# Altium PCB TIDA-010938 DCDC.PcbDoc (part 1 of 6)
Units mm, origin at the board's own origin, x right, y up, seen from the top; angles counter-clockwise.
Board outline 280 x 174.95 mm, 4 copper layers (Top Layer, Layer 1, Layer 2, Bottom Layer), stack 1.787 mm thick; 409 components, 218 nets, 1371 pads, 2268 vias.
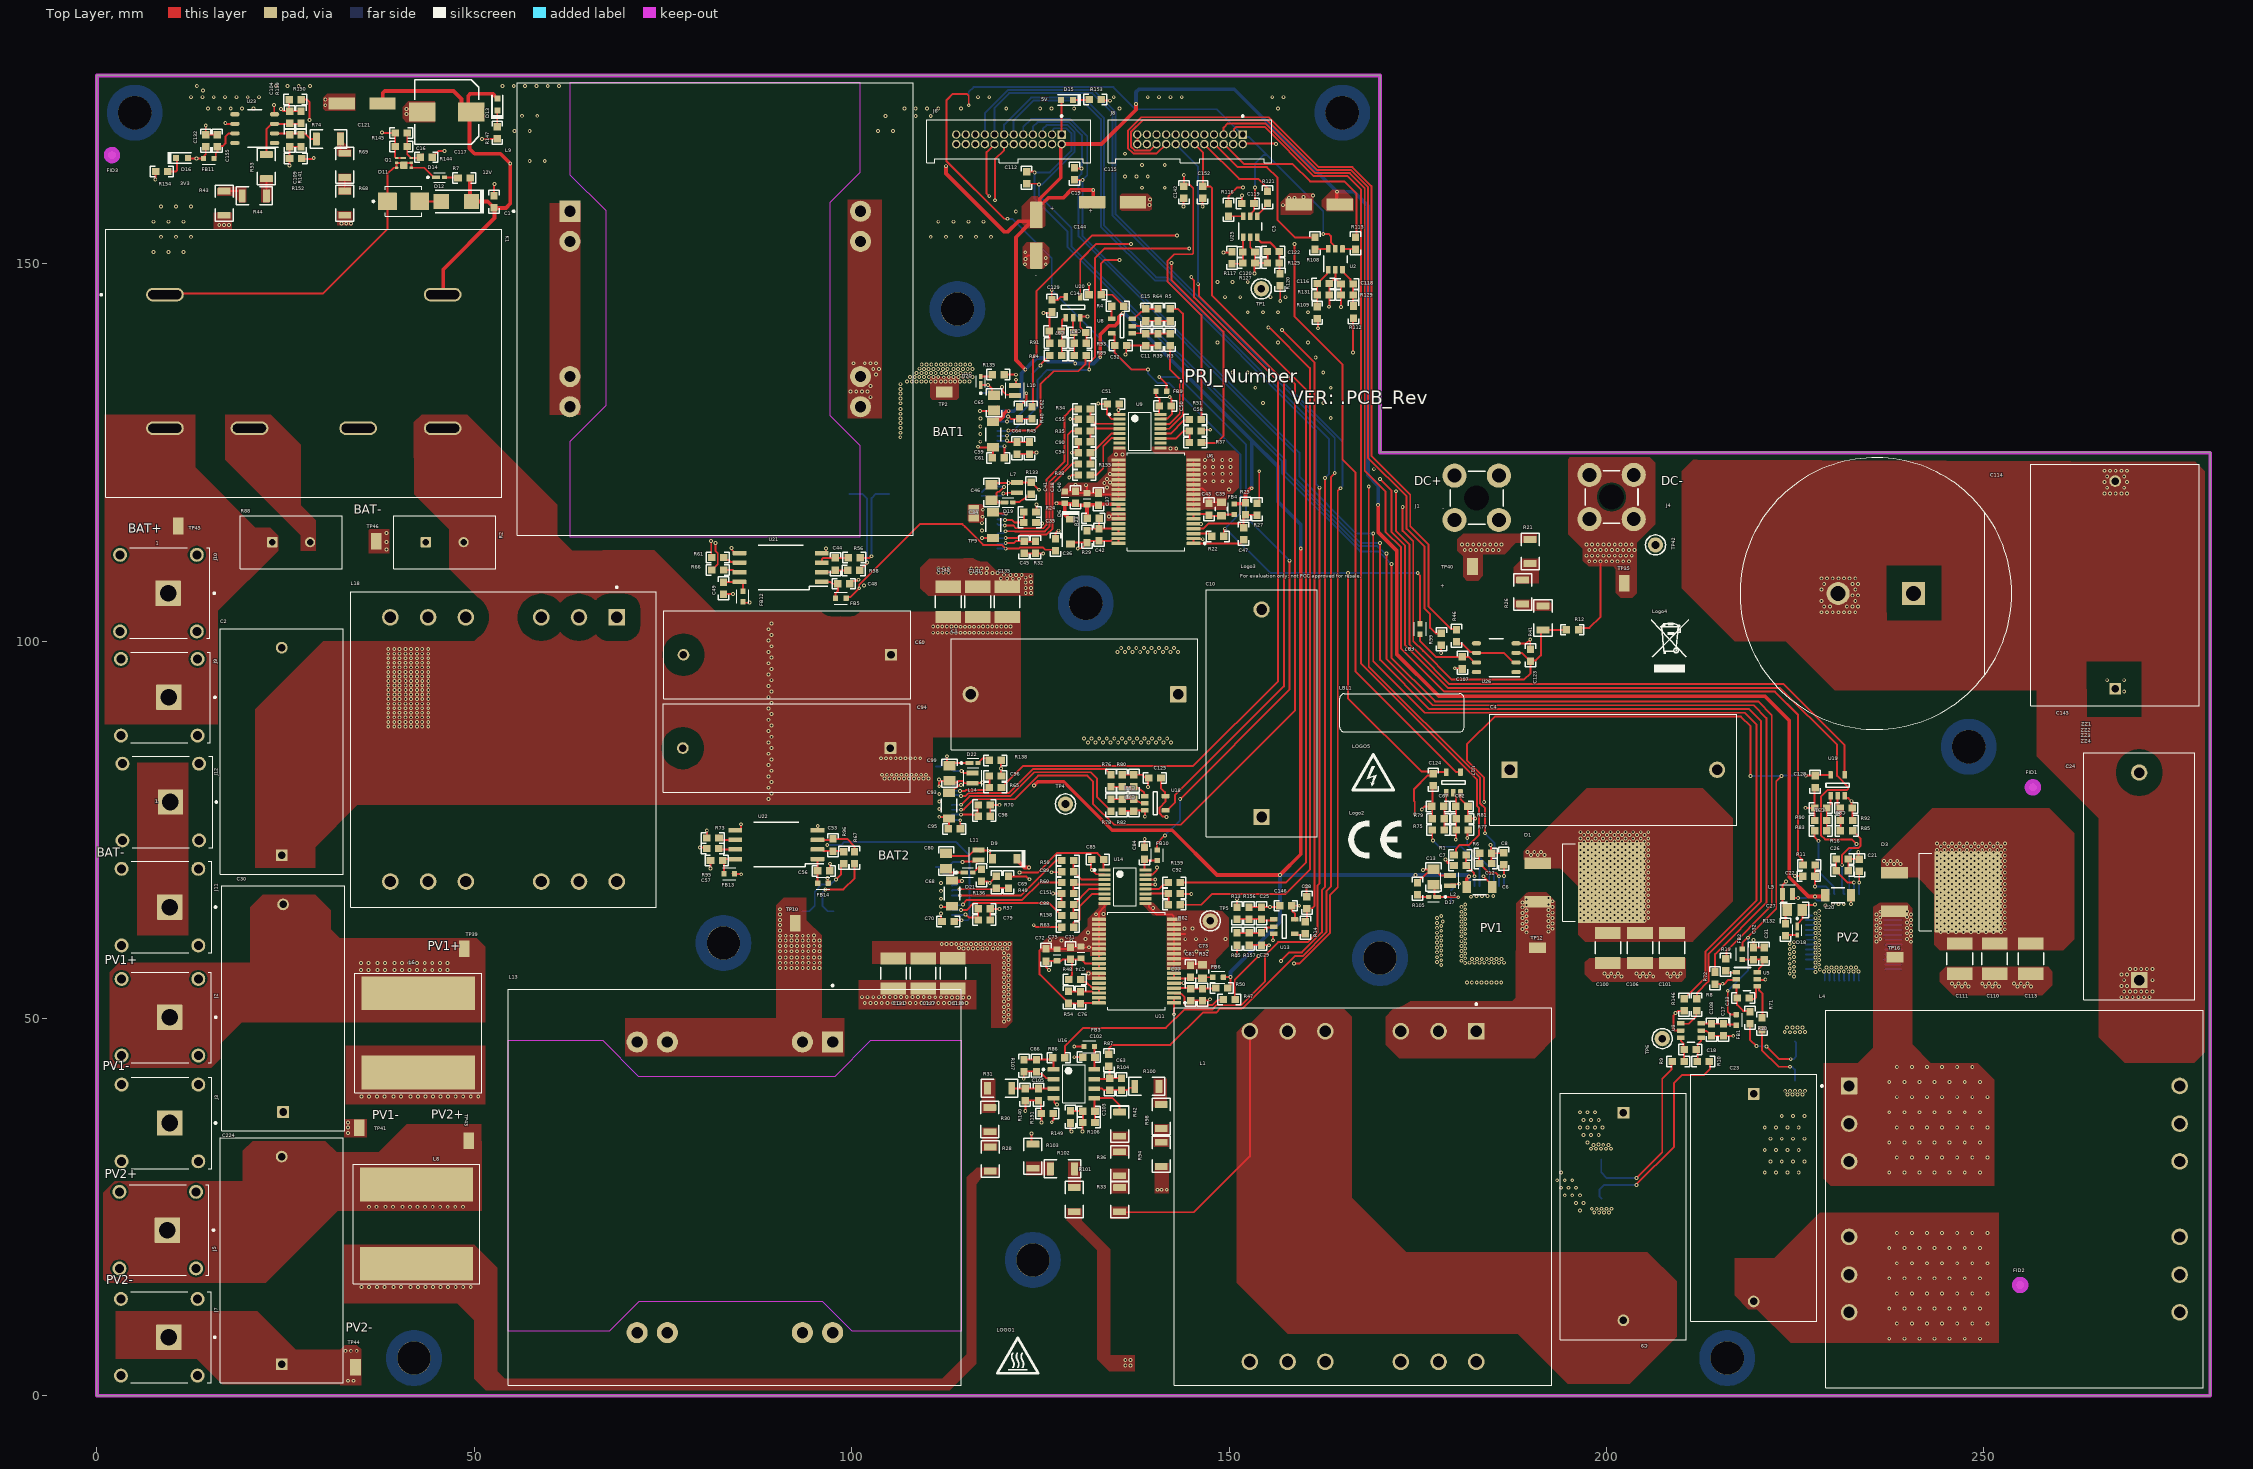
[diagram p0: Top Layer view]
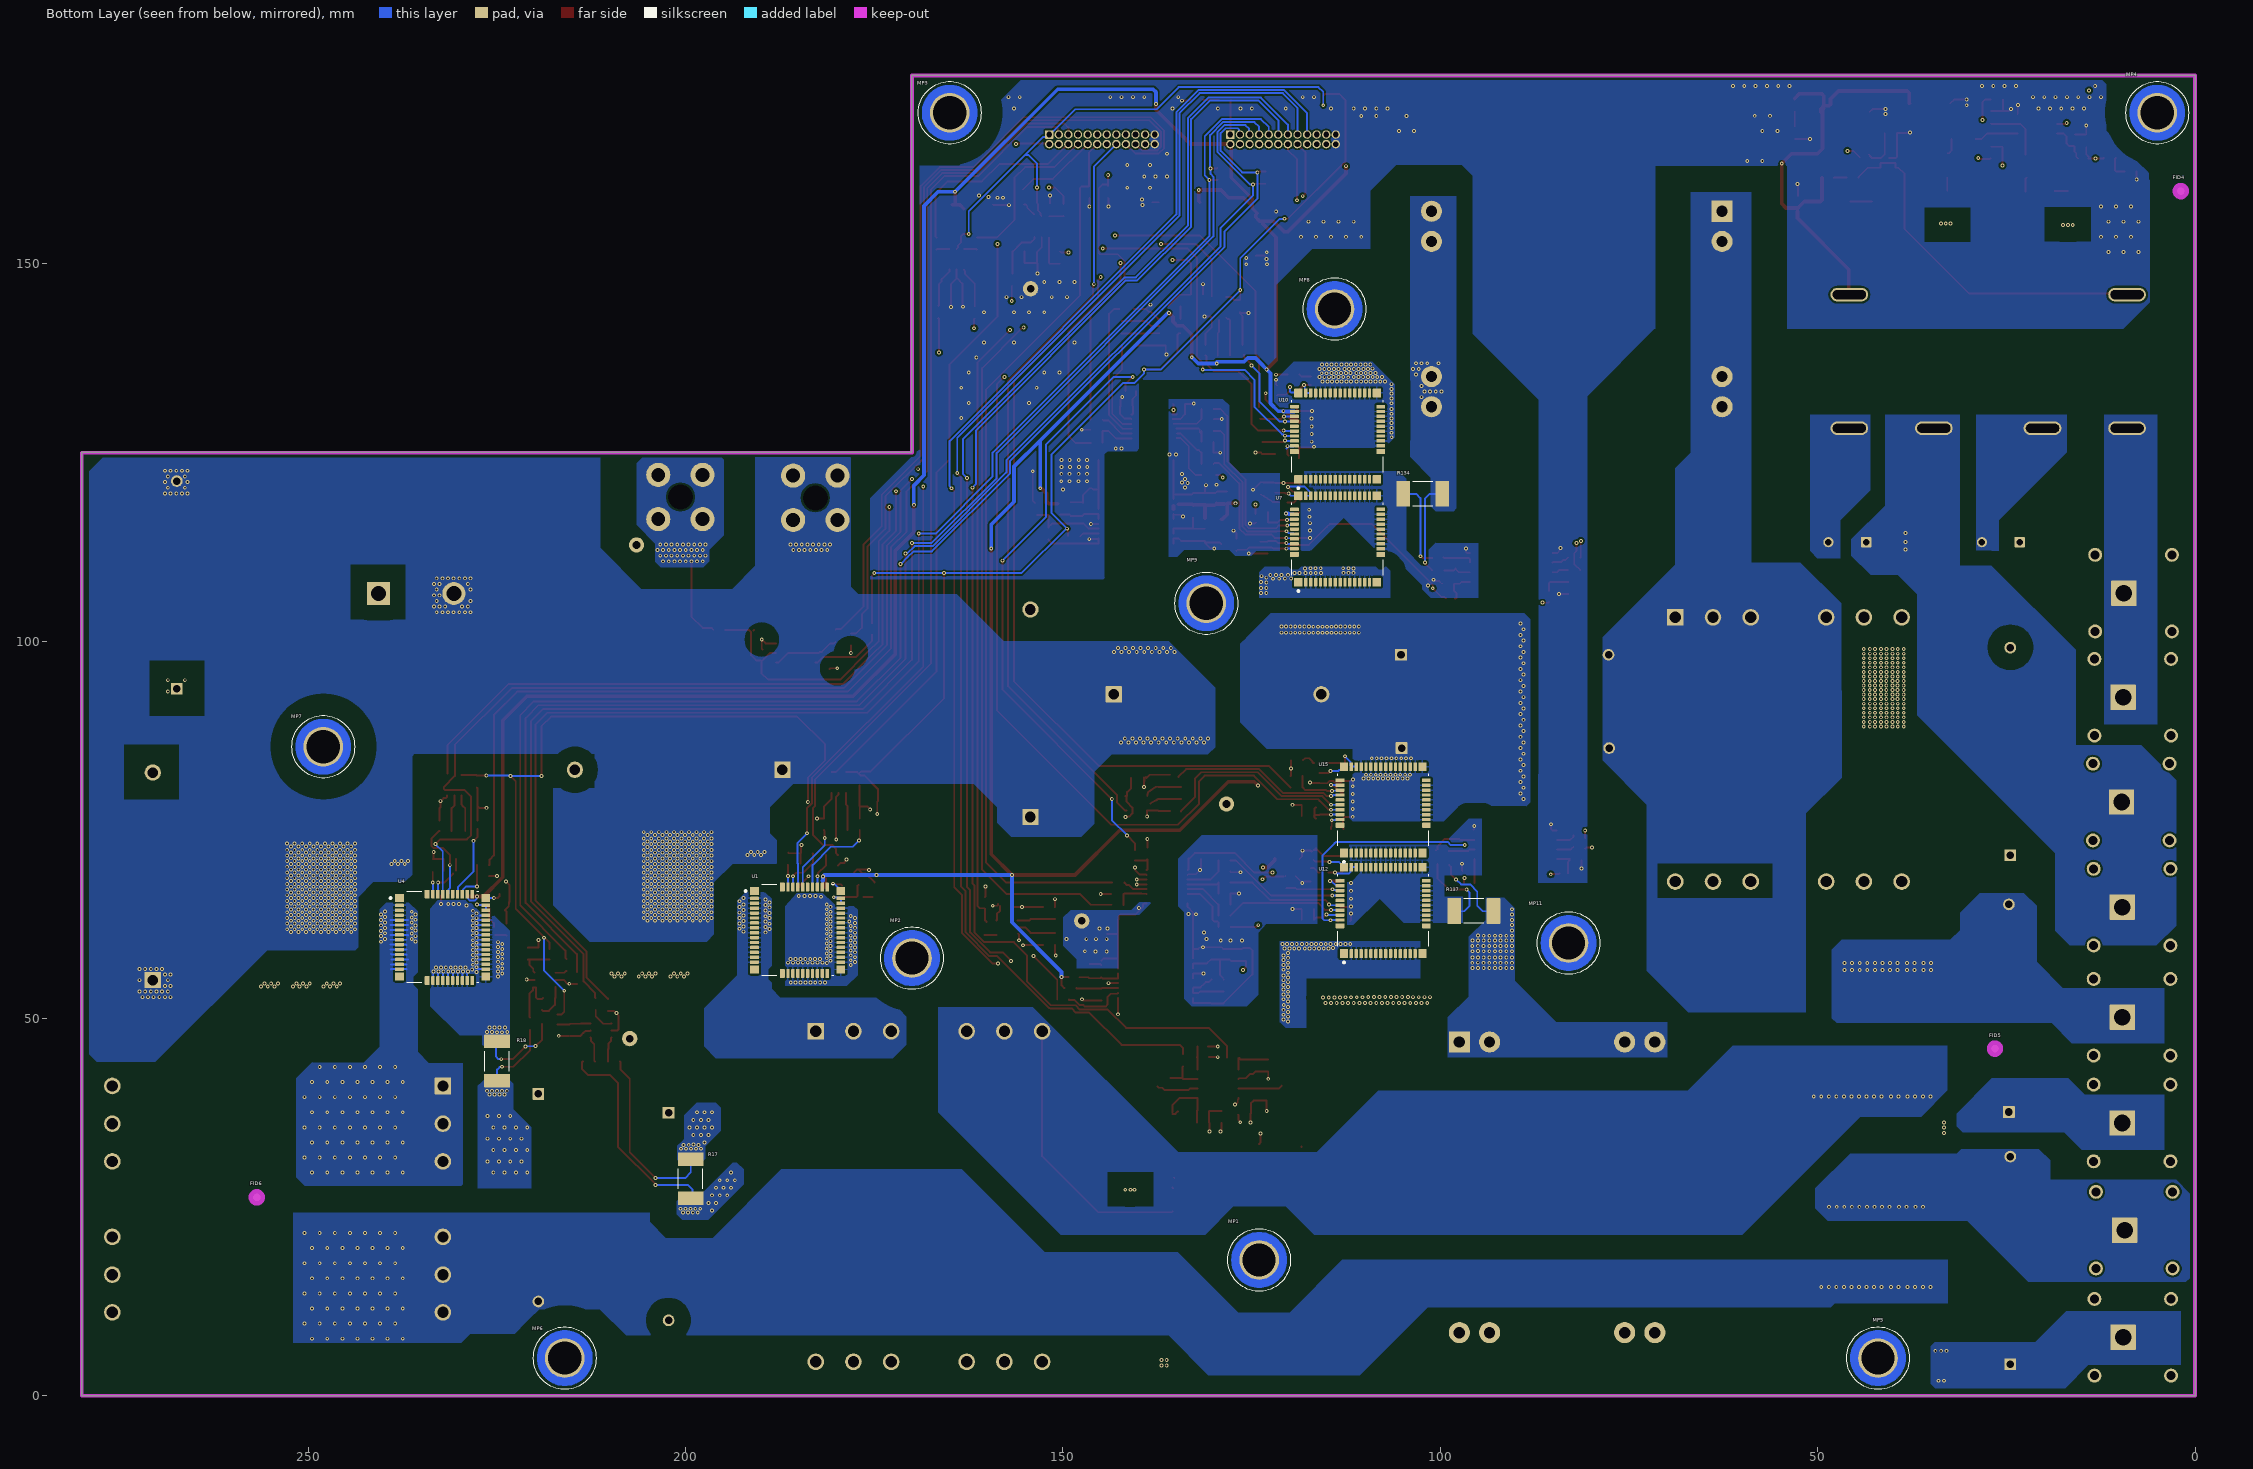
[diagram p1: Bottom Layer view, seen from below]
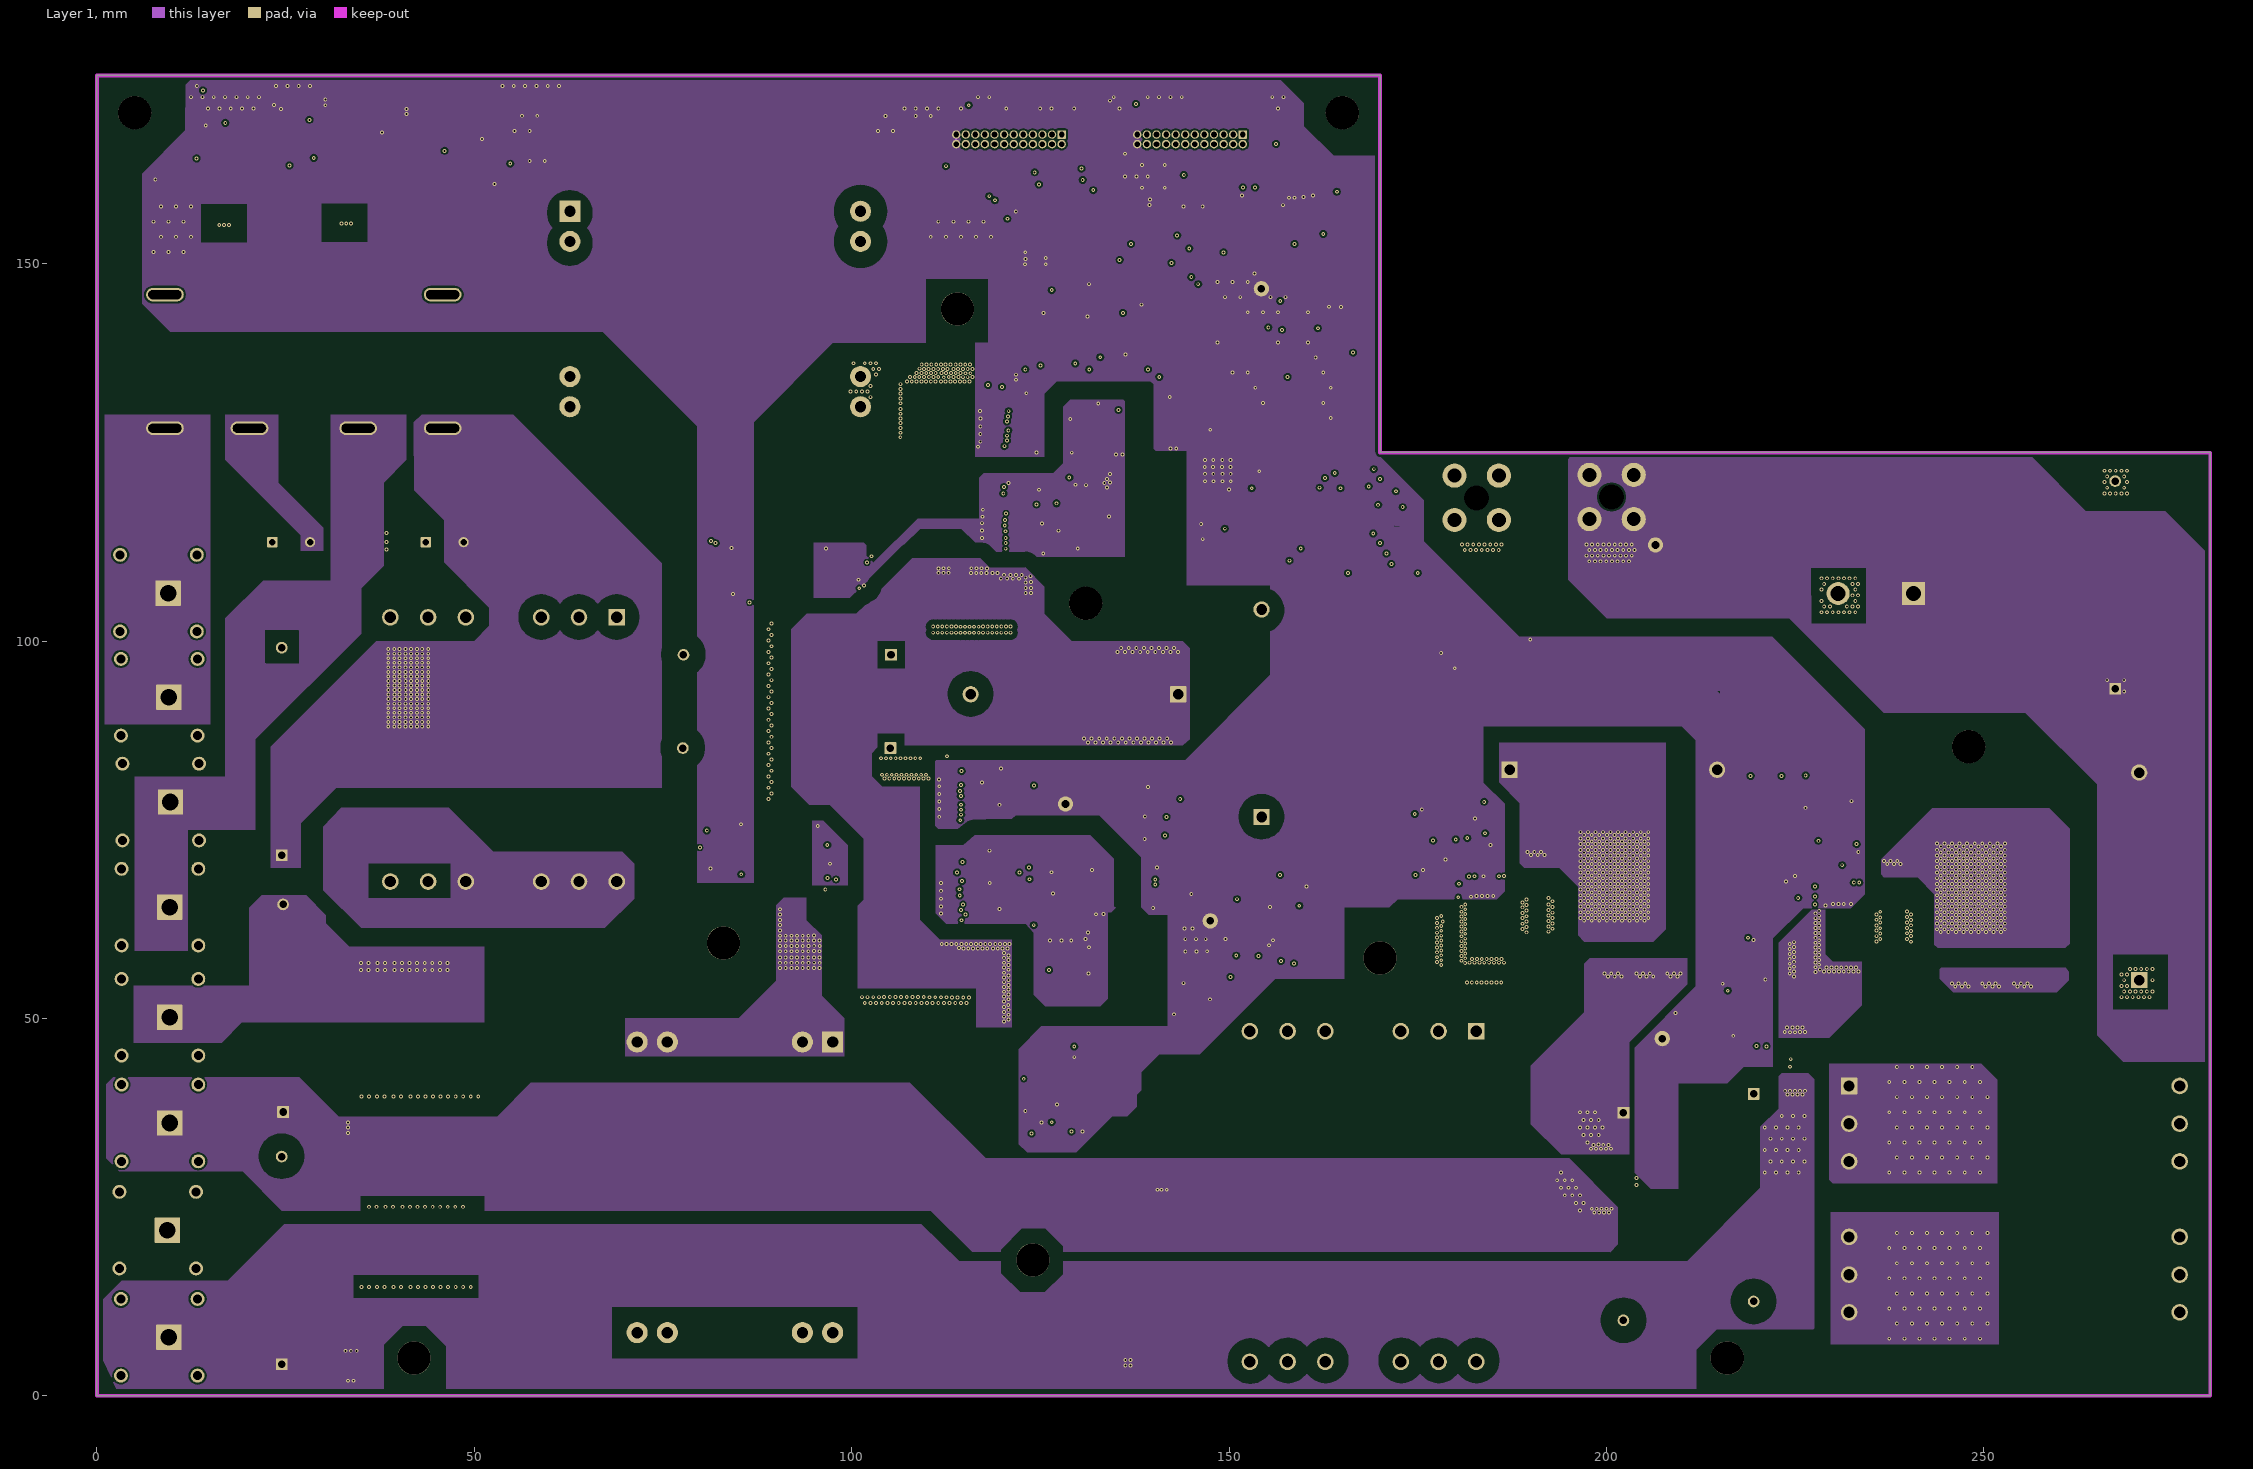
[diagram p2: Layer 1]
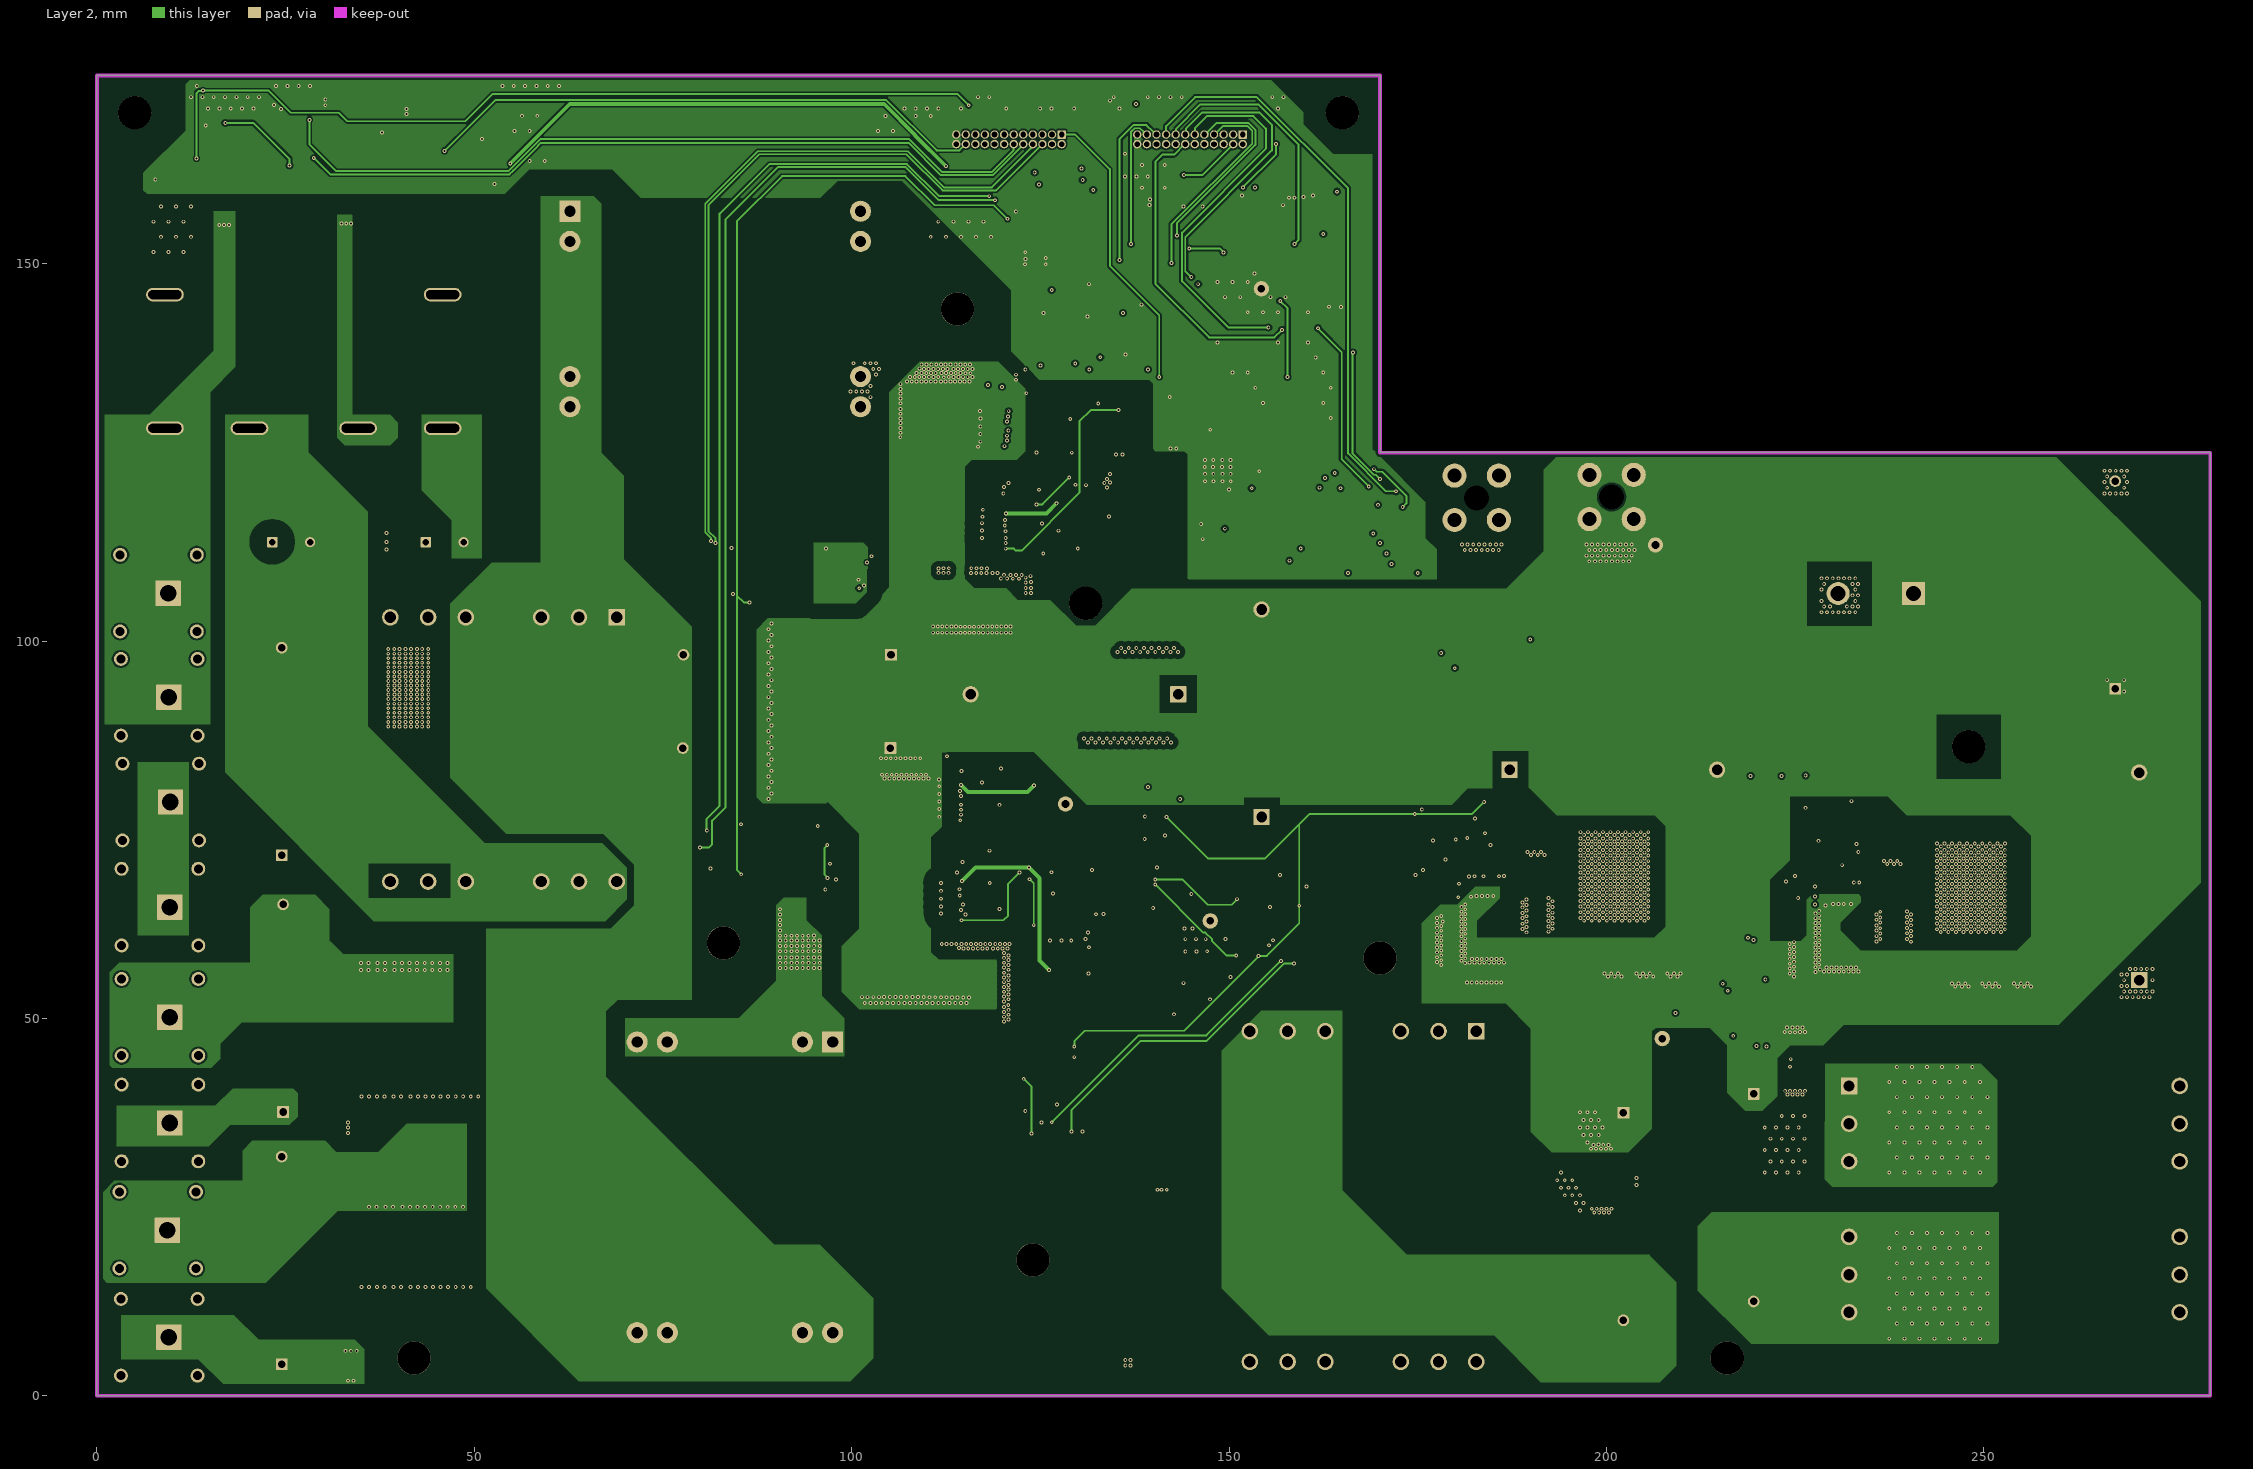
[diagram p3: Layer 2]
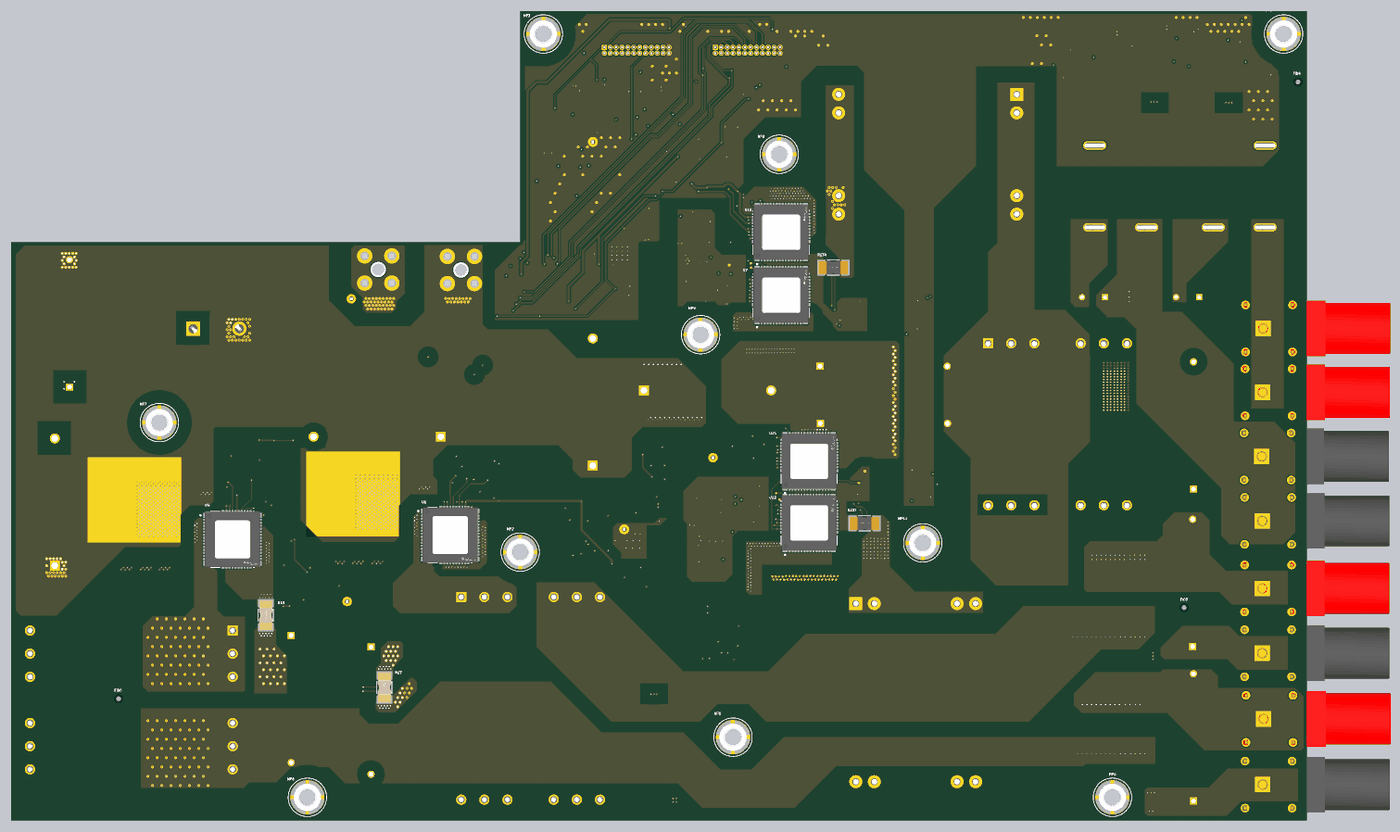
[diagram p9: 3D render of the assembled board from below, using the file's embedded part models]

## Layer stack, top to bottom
Top Solder: solder mask 0.0102, Solder Resist, Dk 3.5
Top Layer: signal copper 0.0356
Dielectric 1: prepreg 0.0711, PP-006, Dk 4.1
Layer 1: signal copper 0.035
Dielectric1: core 1.5037, FR-4 High Tg, Dk 4.8
Layer 2: signal copper 0.035
Dielectric 2: prepreg 0.0711, PP-006, Dk 4.1
Bottom Layer: signal copper 0.0356
Bottom Solder: solder mask 0.0102, Solder Resist, Dk 3.5

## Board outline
280,0 280,125 170,125 170,174.95 0,174.95 0,0

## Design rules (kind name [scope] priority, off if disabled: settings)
AcuteAngle [All] p1: minimum=4.50000000000000E+0001 checktracksonly=FALSE
AssemblyTestPointUsage [All] p1: valid=2
BoardOutlineClearance BoardOutlineClearance_MountingHoles [OnCopper and InComponentClass('Mounting Holes')] p1: gap=1 ignorepadtopadclearanceinfootprint=FALSE
BoardOutlineClearance BoardOutlineClearance_Poly [OnCopper and IsPoly] p2: gap=0.635 ignorepadtopadclearanceinfootprint=FALSE
BoardOutlineClearance [OnCopper and Not InComponentClass('Logo') and not InComponentClass('FiducialMark') and not InRegion(1000,500,4000,800) and not InPoly] p3: gap=1.016 ignorepadtopadclearanceinfootprint=FALSE
Clearance "Clearance Top HVN-HVP2" [InNetClass('HVN') vs (InNetClass('HVP') or InNetClass('Boost1p') or  InNetClass('Boost2p') or InNetClass('BatP') ) and (OnLayer('Top Layer') OR OnLayer('Bottom Layer'))] p1: gap=2 ignorepadtopadclearanceinfootprint=TRUE
Clearance "Clearance Top HVN-HVP" [InNetClass('HVN') AND (OnLayer('Top Layer') OR OnLayer('Bottom Layer')) vs (InNetClass('HVP') or InNetClass('Boost1p') or  InNetClass('Boost2p') or InNetClass('BatP') )] p2: gap=2 ignorepadtopadclearanceinfootprint=TRUE
Clearance GaN_SW [(InNamedPolygon('Layer 2-Bat_IN-')) vs (InNet('SW1') OR InNet('SW2'))] p3: gap=0.7 ignorepadtopadclearanceinfootprint=TRUE
Clearance SW_Bidirect1 [InNetClass('HV_SW_BAT1') vs InNetClass('HVN') or  InNetClass('HVP')] p4: gap=2.1 ignorepadtopadclearanceinfootprint=TRUE
Clearance SW_Bidirect2 [InNetClass('HV_SW_BAT2') vs InNetClass('HVN') or InNetClass('HVP')] p5: gap=2.1 ignorepadtopadclearanceinfootprint=TRUE
Clearance HVN_HVP_GAN [(InNamedPolygon('layer 2-Bat_IN-') AND InNetClass('HVN')) vs (InNamedPolygon('TOP_LAYER_DC_BUS+_P028') AND InNetClass('HVP'))] p6: gap=0.7 ignorepadtopadclearanceinfootprint=TRUE
Clearance HVN_HVP [InNetClass('HVN') vs InNetClass('HVP') or InNetClass('Boost1p') or  InNetClass('Boost2p') or InNetClass('BatP')] p7: gap=0.7 ignorepadtopadclearanceinfootprint=TRUE
Clearance Clearance_Keepouts [((IsTrack Or IsArc) And Not InPoly) And IsFree and IsKeepOut vs ((IsTrack Or IsArc) And Not InPoly) And IsFree and IsKeepOut] p8: gap=0 ignorepadtopadclearanceinfootprint=FALSE
Clearance Clearance_Poly [InPolygon] p9: gap=0.254 ignorepadtopadclearanceinfootprint=TRUE
Clearance Clearance_FiducialMark [IsKeepOut and InComponentClass('FiducialMark') vs IsPad and InComponentClass('FiducialMark')] p10: gap=0 ignorepadtopadclearanceinfootprint=TRUE
Clearance "Minimum distance" [All] p11: gap=0.15 ignorepadtopadclearanceinfootprint=TRUE
ComponentClearance ComponentClearance_MountingHoles_FiducialMarks [InComponentClass('Mounting Holes') vs InComponentClass('FiducialMark')] p1: gap=1.27 collisioncheckmode=3 verticalgap=0.254 showdistances=FALSE
ComponentClearance ComponentClearance_Shunt [InComponentClass('Header') vs InComponentClass('Shunt')] p2: gap=0 collisioncheckmode=3 verticalgap=0 showdistances=FALSE
ComponentClearance ComponentClearance_Logo [InComponentClass('Logo')] p3: gap=0.762 collisioncheckmode=3 verticalgap=0.254 showdistances=FALSE
ComponentClearance ComponentClearance_ScrewToNut [(HasFootprint('NY PMS 440 0025 PH')) vs (HasFootprint('Keystone_1902C'))] p4: gap=0.127 collisioncheckmode=3 verticalgap=0.254 showdistances=FALSE
ComponentClearance ComponentClearance_MountingHoles [InComponentClass('Mounting Holes')] p5: gap=2.54 collisioncheckmode=3 verticalgap=2540 showdistances=FALSE
ComponentClearance ComponentClearance_SmallPassives [HasFootprint('0201*') or HasFootprint('0402*') or HasFootprint('0508') or HasFootprint('0603*') or HasFootprint('0612') or HasFootprint('0805*') or HasFootprint('0815*') or HasFootprint('0830*') or HasFootprint('1206*') or HasFootprint('1210*') or HasFootprint('1808*') or HasFootprint('1812*') or HasFootprint('1825*') or HasFootprint('2010*') or HasFootprint('2220*') or HasFootprint('2225*') or HasFootprint('2512*') or HasFootprint('2728*') or HasFootprint('3518*') vs HasFootprint('0201*') or HasFootprint('0402*') or HasFootprint('0508') or HasFootprint('0603*') or HasFootprint('0612') or HasFootprint('0805*') or HasFootprint('0815*') or HasFootprint('0830*') or HasFootprint('1206*') or HasFootprint('1210*') or HasFootprint('1808*') or HasFootprint('1812*') or HasFootprint('1825*') or HasFootprint('2010*') or HasFootprint('2220*') or HasFootprint('2225*') or HasFootprint('2512*') or HasFootprint('2728*') or HasFootprint('3518*')] p6: gap=0.38 collisioncheckmode=3 verticalgap=0.254 showdistances=FALSE
ComponentClearance ComponentClearance_THtoSMT [IsThruComponent vs IsSMTComponent] p7: gap=0.762 collisioncheckmode=3 verticalgap=0.762 showdistances=FALSE
ComponentClearance ComponentClearance_THtoTH [IsThruComponent vs IsThruComponent] p8: gap=0.508 collisioncheckmode=3 verticalgap=0.762 showdistances=FALSE
ComponentClearance [All] p9: gap=0.508 collisioncheckmode=3 verticalgap=0.254 showdistances=FALSE
DiffPairsRouting [All] p1: maxlimit=2.54 minlimit=0.254 mostfreqgap=0.254 toplayer_minwidth=0.381 toplayer_maxwidth=0.381 toplayer_prefwidth=0.381 midlayer1_minwidth=0.381 midlayer1_maxwidth=0.381 midlayer1_prefwidth=0.381 midlayer2_minwidth=0.381 midlayer2_maxwidth=0.381 midlayer2_prefwidth=0.381 bottomlayer_minwidth=0.381 bottomlayer_maxwidth=0.381 bottomlayer_prefwidth=0.381 maxuncoupledlength=25.4
FabricationTestPointUsage TestPointUsage [All] p1: valid=2 allowmultiple=FALSE
FabricationTestpoint Testpoint [All] p1: side=3 testpointundercomponent=TRUE minsize=1.016 maxsize=2.54 preferedsize=1.524 minholesize=0 maxholesize=1.016 preferedholesize=0.813 testpointgrid=0.025 allowsidetop=TRUE allowsidebottom=TRUE usegrid=TRUE gridtolerance=0
FanoutControl Fanout_LCC [IsLCC] p1: bgadir=Out bgaviamode=Centered fanoutstyle=Auto fanoutdirection=Alternating viagrid=0.025 // Fanout_LCC (Default Rule)
FanoutControl Fanout_BGA [IsBGA] p2: bgadir=Out bgaviamode=Centered fanoutstyle=Auto fanoutdirection=Alternating viagrid=0.025 // Fanout_BGA (Default Rule)
FanoutControl Fanout_Default [All] p4: bgadir=Out bgaviamode=Centered fanoutstyle=Auto fanoutdirection=Alternating viagrid=0.025 // Fanout_Default (Default Rule)
FanoutControl Fanout_Small [(CompPinCount < 5)] p5: bgadir=Out bgaviamode=Centered fanoutstyle=Auto fanoutdirection=OutThenIn viagrid=0.025 // Fanout_Small (Default Rule)
HoleSize [All] p1: absolutevalues=TRUE maxlimit=6.375 minlimit=0.2 maxpercent=80.000 minpercent=20.000
MinimumAnnularRing MinimumAnnularRing_ThermalPadVias [IsVia and InAnyComponent] p1: minimumring=0.15
MinimumAnnularRing [All] p2: minimumring=0.125
MinimumSolderMaskSliver MinimumSolderMaskSliver_Logo [InComponentClass('Logo') vs InComponentClass('Logo')] p1: minsoldermaskwidth=0.018
MinimumSolderMaskSliver [All] p2: minsoldermaskwidth=0.1
PlaneConnect [All] p1: planeconnectstyle=Direct reliefexpansion=0.254 reliefentries=4 reliefconductorwidth=0.254 reliefairgap=0.254
PolygonConnect "GaN 1" [IsNamedPolygon('BOTTOM_LAYER_BAT_IN-_P103') or    IsNamedPolygon('BOTTOM_LAYER_BAT_IN-_P061')  or IsNamedPolygon('BOTTOM_LAYER_DC_BUS+_P120')    or IsNamedPolygon('Bottom Layer-NetD1_2')   or IsNamedPolygon('Bottom Layer-NetD3_2')   or IsNamedPolygon('BOTTOM_LAYER_DC_BUS-_P046') or IsNamedPolygon('BOTTOM_LAYER_BAT_IN-_P061') or IsNamedPolygon('BOTTOM_LAYER_DC_BUS+_P027') or IsNamedPolygon('gan1_sw') or IsNamedPolygon('gan2_sw')      or IsNamedPolygon('BOTTOM_LAYER_DC_BUS-_P045') or IsNamedPolygon('BOTTOM_LAYER_GND_BAT_P061') or  IsNamedPolygon('Bottom_Layer-Bat_IN-') or IsNamedPolygon('BOTTOM_LAYER_DC_BUS-_P061') or IsNamedPolygon('Bottom Layer-SW1') vs HasFootprint('RQS0052C-C01-MFG')] p1: thpad.connectstyle=Direct thpad.reliefconductorwidth=1 thpad.reliefentries=4 thpad.polygonreliefangle="90 Angle" thpad.airgapwidth=0.254 smdpad.connectstyle=Relief smdpad.reliefconductorwidth=0.254 smdpad.reliefentries=4 smdpad.polygonreliefangle="90 Angle" smdpad.airgapwidth=0.254 via.connectstyle=Direct via.reliefconductorwidth=0.254 via.reliefentries=4 via.polygonreliefangle="90 Angle" via.airgapwidth=0.254
PolygonConnect PolygonConnect_1 [All] p2: connectstyle=Direct reliefconductorwidth=1 reliefentries=4 polygonreliefangle="90 Angle" airgapwidth=0.254
RoutingVias ThermalPadVias [IsVia and InAnyComponent] p1: holewidth=0.254 width=0.508 viastyle="Through Hole" minholewidth=0.2 minwidth=0.5 maxholewidth=1.016 maxwidth=1.651
RoutingVias [All] p2: holewidth=0.406 width=0.864 viastyle="Through Hole" minholewidth=0.2 minwidth=0.61 maxholewidth=1.016 maxwidth=1.651
SilkToBoardRegionClearance [Not ((IsComment or IsDesignator) And (Hide <> 'False')) and not InRegion(1000,500,4000,800)] p1:
SilkToSilkClearance SilkToSilkClearance_Pb-FreeLogo [(HasFootprint('Pb-Free_Overlay_Medium') OR HasFootprint('Pb-Free_Overlay_Small')) vs (HasFootprint('Pb-Free_Overlay_Medium') OR HasFootprint('Pb-Free_Overlay_Small'))] p1: silktosilkclearance=0
SilkToSilkClearance [All] p2: silktosilkclearance=0.1
SilkToSolderMaskClearance SilkToComponentPadClearance [(IsPad or IsFill or IsRegion) and InAnycomponent] p1: minsilkscreentomaskgap=0.01 clearancetoexposedcopper=TRUE
SilkToSolderMaskClearance "Silk to Solder Mask Opening" [All] p2: minsilkscreentomaskgap=0.01 clearancetoexposedcopper=FALSE
SolderMaskExpansion [All] p1: expansion=0.05 istentingtop=FALSE
UnRoutedNet [All] p1: checkbadconnections=TRUE
Width Width12V [InNet('12V_HVN') or  InNet('12V_SW1') or InNet('12V_SW2')] p1: maxlimit=2.54 minlimit=0.25 preferedwidth=0.5
Width Width_1 [All] p2: maxlimit=0.254 minlimit=0.254 preferedwidth=0.254
14 further rules are at their usual default settings.

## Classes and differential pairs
component class Designator: !PCB FID1 FID2 FID3 FID4 FID5 FID6 LBL1 LOGO1 Logo2 Logo3 Logo4 LOGO5 MP1 MP2 MP3 MP4 MP5 MP6 MP7 MP8 MP9 MP11 ZZ1 ZZ2 ZZ3 ZZ4
component class Designator: C63 C66 C102 C103 C104 C105 C107 C109 C123 C155 FB3 FB7 FB11 R12 R21 R26 R28 R30 R31 R33 R36 R41 R42 R43 R44 R46 R53 R68 R69 R74 R86 R87 R94 R98 R99 R100 R101 R102 R103 R104 R106 R107 R139 R140 R141 R149 R150 R151 R152 U16 U23 U26
component class Designator: C67 C78 C82 C83 C86 C87 C91 C97 C116 C118 C119 C120 C122 C124 C125 C128 C129 C132 R75 R76 R77 R78 R79 R80 R81 R82 R83 R84 R85 R89 R90 R91 R92 R93 R108 R109 R112 R113 R116 R117 R120 R121 R125 R127 R129 R131 U2 U17 U18 U19 U20 U25
component class Designator: C5 C6 C7 C8 C9 C10 C12 C13 C17 C18 C19 C30 C100 C101 C106 C108 D1 D17 FB1 L1 L2 L6 R1 R6 R8 R9 R10 R17 R105 R146 TP12 U1 U3
component class Designator: C25 C28 C29 C53 C56 C57 C68 C69 C70 C71 C72 C73 C74 C75 C76 C77 C79 C80 C81 C84 C85 C88 C89 C92 C93 C94 C95 C96 C98 C99 C121 C135 C140 C141 C146 C151 C152 D9 D21 D22 FB6 FB10 FB13 FB14 L11 L13 L14 R13 R14 R15 R47 R48 R49 R50 R52 R54 R57 R59 R60 R62 R63 R65 R67 R70 R73 R95 R96 R136 R137 R138 R156 R157 R158 R159 TP4 TP5 TP10 U11 U12 U13 U14 U15 U22
component class Designator: C11 C14 C15 C34 C35 C36 C37 C38 C39 C40 C41 C42 C43 C44 C45 C46 C47 C48 C49 C50 C51 C52 C54 C55 C58 C59 C60 C61 C62 C64 C65 C90 C115 C127 C130 C131 C142 D6 D19 D20 FB4 FB5 FB9 FB12 L7 L9 L10 R3 R4 R5 R22 R23 R24 R25 R27 R29 R32 R34 R35 R37 R38 R39 R40 R45 R51 R56 R58 R61 R64 R66 R133 R134 R135 R155 TP1 TP6 TP9 U6 U7 U8 U9 U10 U21
net class HVP: DC_Bus+
net class Boost2SW: NetD3_2
net class Boost2p: Boost2_IN+ "PV2 Bus+"
net class Boost1SW: NetD1_2
net class Boost1p: Boost1_IN+ "PV1 Bus+"
net class BatP: "BAT Bus+" BatIN+ NetC2_2
net class HV_SW_BAT2: 5V_SW2 12V_SW2 F\A\U\L\T\_Bat_H2_init IN_PWM_Bat_H2 NetC53_1 NetC53_2 NetC56_1 NetC69_2 NetC76_1 NetC79_2 NetC80_1 NetC88_2 NetC89_2 NetC151_2 NetD21_2 NetL11_2 NetL13_1 NetR63_1 NetU11_32 NetU12_17 NetU12_27 NetU12_43 NetU12_47 NetU12_52 NetU14_7 NetU15_1 NetU15_16 O\C\_Bat_H2_init SW2 TEMP_Bat_H2_init
net class HV_SW_BAT1: 5V_SW1 12V_SW1 F\A\U\L\T\_Bat_H1_init IN_PWM_Bat_H1 NetC35_2 NetC42_1 NetC44_1 NetC44_2 NetC45_2 NetC46_1 NetC48_1 NetC54_2 NetC55_2 NetC90_2 NetD19_2 NetL7_2 NetL9_5 NetR38_1 NetU6_32 NetU7_17 NetU7_27 NetU7_43 NetU7_47 NetU7_52 NetU9_7 NetU10_1 NetU10_16 O\C\_Bat_H1_init SW1 TEMP_Bat_H1_init
net class PE: NetMP1_1 NetMP2_1 NetMP3_1 NetMP4_1 NetMP5_1 NetMP6_1 NetMP7_1 NetMP8_1
component class Label: LBL1
component class FiducialMark: FID1 FID2 FID3 FID4 FID5 FID6
component class AssemblyNote: ZZ1 ZZ2 ZZ3 ZZ4
net class HVN: 3V3_HVN 5V_HVN 12V_HVN "BAT Bus-" Batt_H1_Buff Batt_H2_Buff Batt_L1_Buff Batt_L2_Buff Boost_S1_Buff Boost_S2_Buff CS_Batt1+ CS_Batt1- CS_Batt2+ CS_Batt2- CS_Boost1+ CS_Boost1- CS_Boost2+ CS_Boost2- DC_Bus- Enable_Buffer_DCDC F\A\U\L\T\__Bat_H1_Buff F\A\U\L\T\_Bat_H2_Buff F\A\U\L\T\_Bat_L1_init F\A\U\L\T\_Bat_L2_init F\A\U\L\T\_Boost1_init F\A\U\L\T\_Boost2_init F\A\U\L\T\_O\C\_Batt_H1_Buff F\A\U\L\T\_O\C\_Batt_H2_Buff F\A\U\L\T\_O\C\_Batt_L1_Buff F\A\U\L\T\_O\C\_Batt_L2_Buff F\A\U\L\T\_O\C\_Boost1_Buff F\A\U\L\T\_O\C\_Boost2_Buff NetC7_2 NetC8_2 NetC11_2 NetC12_2 NetC13_1 NetC15_2 NetC16_1 NetC17_1 NetC18_1 NetC18_2 NetC21_2 NetC22_2 NetC25_2 NetC26_2 NetC27_1 NetC29_2 NetC31_2 NetC33_1 NetC33_2 NetC39_2 NetC47_2 NetC49_1 NetC50_2 NetC57_1 NetC58_2 NetC61_2 NetC62_2 NetC64_2 NetC65_1 NetC66_1 NetC66_2 NetC67_1 NetC73_2 NetC78_1 NetC81_2 NetC82_1 NetC83_1 NetC84_2 NetC86_1 NetC87_1 NetC91_1 NetC92_2 NetC95_2 NetC96_2 NetC97_1 NetC98_2 NetC99_1 NetC102_2 NetC105_2 NetC107_2 NetC116_2 NetC118_2 NetC120_2 NetC122_2 NetC123_2 NetD11_2 NetD13_1 NetD14_2 NetD15_1 NetD16_1 NetD17_2 NetD18_2 NetD20_2 NetD22_2 NetL2_2 NetL5_2 NetL10_2 NetL14_2 NetR4_1 NetR8_1 NetR14_1 NetR19_1 NetR22_2 NetR46_1 NetR47_2 NetR51_2 NetR61_2 NetR66_2 NetR73_2 NetR95_2 NetR108_1 NetR113_1 NetR116_1 NetR121_1 NetR159_2 O\C\__Bat_H1_Buff O\C\_Bat_H2_Buff O\C\_Bat_L1_init O\C\_Bat_L2_init O\C\_Boost1_init O\C\_Boost2_init "PV1 Bus-" "PV2 Bus-" RY_DCPreCharge SN_DCPreCharge TEMP_Bat_L1_init TEMP_Bat_L2_init TEMP_Batt_H1_Buff TEMP_Batt_H2_Buff TEMP_Batt_L1_Buff TEMP_Batt_L2_Buff TEMP_Boost1_Buff TEMP_Boost1_init TEMP_Boost2_Buff TEMP_Boost2_init VS_Batt1+ VS_Batt1- VS_Boost1+ VS_Boost1- VS_Boost2+ VS_Boost2- VS_DCDC_VDC+ VS_DCDC_VDC-
component class Designator: 90 C1 C2 C3 C4 C16 C114 C117 C143 C144 D11 D12 D13 D14 D15 D16 J1 J2 J3 J4 J5 J6 J7 J8 J9 J10 J11 J12 K1 L18 Q1 R2 R7 R88 R144 R145 R147 R153 R154 TP2 TP35 TP39 TP40 TP41 TP42 TP43 TP44 TP45 TP46
component class Designator: C20 C21 C22 C23 C24 C26 C27 C31 C32 C33 C110 C111 C112 C113 C224 D3 D18 FB2 L4 L5 L8 R11 R16 R18 R19 R20 R71 R72 R132 TP16 U4 U5

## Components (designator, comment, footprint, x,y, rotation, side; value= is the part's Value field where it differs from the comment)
C1 "06033C104JAT2A" 0603 52.616,158.2 r270 top value=0.1uF
C2 "R533R456050P0M" FP-R533R456050P0M_RADIAL-MFG 24.468,85.381 r90 top locked value=5.6µF
C3 "C4AKOBU4270A3YJ" FP-C4AKOBU4270A3YJ_RADIAL-MFG 129.508,92.95 r180 top locked value=2.7µF
C4 "C4AKOBU4270A3YJ" FP-C4AKOBU4270A3YJ_RADIAL-MFG 200.91,82.95 r0 top locked value=2.7µF
C5 "UWT1E101MCL1GS" UWT_630x770 161.946,157.828 r180 top value=100uF
C6 "TMK316AB7106KLHT" 1206_180 183.186,67.409 r0 top value=10uF
C7 "GRM188R71H221KA01D" 0603 180.601,70.262 r0 top value=220pF
C8 "06033C104JAT2A" 0603 186.392,71.165 r270 top value=0.1uF
C9 "C4AUJBU4600M18J" FP-C4AUJBU4600M18J_RADIAL-MFG 202.249,23.746 r270 top value=6µF
C10 "C4AKOBU4270A3YJ" FP-C4AKOBU4270A3YJ_RADIAL-MFG 154.304,90.438 r90 top locked value=2.7µF
C11 "GRM188R71H221KA01D" 0603 138.968,139.948 r90 top value=220pF
C12 "GRM188R71H221KA01D" 0603 183.976,70.518 r180 top value=220pF
C13 "CGA4J3X7R1E225K125AB" 0805_HV 177.062,68.734 r90 top value=2.2uF
C14 "GRM188R71H221KA01D" 0603 132.236,145.886 r0 top value=220pF
C15 "GRM188R71H221KA01D" 0603 138.966,143.21 r270 top value=220pF
C16 "GRM188R72A104KA35J" 0603 40.302,165.52 r180 top value=0.1uF
C17 "TMK107BJ105KA-T" 0603 215.5,48.5 r270 top value=1uF
C18 "885012206089" 0603 211.1,45.9 r180 top value=0.01uF
C19 "GRM188R71H221KA01D" 0603 129.5,161.9 r90 top value=220pF
C20 "TMK316AB7106KLHT" 1206_180 230.694,66.321 r0 top value=10uF
C21 "06033C104JAT2A" 0603 233.5,70.3 r270 top value=0.1uF
C22 "GRM188R71H221KA01D" 0603 226.829,68.837 r0 top value=220pF
C23 "C4AUJBU4600M18J" FP-C4AUJBU4600M18J_RADIAL-MFG 219.5,26.25 r270 top value=6µF
C24 "C4AKOBU4270A3YJ" FP-C4AKOBU4270A3YJ_RADIAL-MFG 270.59,68.831 r90 top value=2.7µF
C25 "GRM188R71H221KA01D" 0603 154.276,63.951 r270 top value=220pF
C26 "GRM188R71H221KA01D" 0603 231.232,69.563 r180 top value=220pF
C27 "CGA4J3X7R1E225K125AB" 0805_HV 224.95,64.365 r180 top value=2.2uF
C28 "GRM188R71H221KA01D" 0603 160.3,65.315 r270 top value=220pF
C29 "GRM188R71H221KA01D" 0603 154.278,60.528 r90 top value=220pF
C30 "R533R456050P0M" FP-R533R456050P0M_RADIAL-MFG 24.653,51.356 r90 top value=5.6µF
C31 "06033C104JAT2A" 0603 220.9,58.6 r270 top value=0.1uF
C32 "TMK107BJ105KA-T" 0603 219.5,58.6 r90 top value=1uF
C33 "885012206089" 0603 218.1,52.7 r180 top value=0.01uF
C34 "TMK316AB7106KLHT" 1206_180 118.742,115.362 r270 top value=10uF
C35 "GRM188R71H221KA01D" 0603 123.618,115.702 r180 top value=220pF
C36 "06033C104JAT2A" 0603 127,112.757 r270 top value=0.1uF
C37 "06033C104JAT2A" 0603 132.705,118.822 r270 top value=0.1uF
C38 "TMK107BJ105KA-T" 0603 129.665,119.049 r270 top value=1uF
C39 "GRMJN7R61C206ME05" 0704 148.966,117.49 r270 top value=20uF
C40 "ZRB18AR61E106ME01L" FP-ZRB18AR61E106ME01L_0603-MFG 131.168,118.846 r90 top value=10µF
C41 "ZRB18AR61E106ME01L" FP-ZRB18AR61E106ME01L_0603-MFG 128.23,119.049 r90 top value=10µF
C42 "GRM1885C1H331JA01D" 0603 132.78,114.084 r270 top value=330pF
C43 "06033C104JAT2A" 0603 147.328,117.483 r270 top value=0.1uF
C44 "885012206089" 0603 97.825,110.212 r90 top value=0.01uF
C45 "GRM188R71H221KA01D" 0603 122.856,112.415 r90 top value=220pF
C46 "CGA4J3X7R1E225K125AB" 0805_HV 118.535,119.683 r90 top value=2.2uF
C47 "885012206089" 0603 151.933,114.24 r90 top value=0.01uF
C48 "06033C104JAT2A" 0603 98.956,107.597 r0 top value=0.1uF
C49 "06033C104JAT2A" 0603 83,107 r270 top value=0.1uF
C50 "06033C104JAT2A" 0603 141.516,131.162 r180 top value=0.1uF
C51 "06033C104JAT2A" 0603 134.649,131.431 r0 top value=0.1uF
C52 "06033C104JAT2A" 0603 135.631,139.148 r0 top value=0.1uF
C53 "885012206089" 0603 97.505,72.98 r90 top value=0.01uF
C54 "GRM188R71H221KA01D" 0603 130.839,124.963 r0 top value=220pF
C55 "GRM188R71H221KA01D" 0603 130.839,129.389 r0 top value=220pF
C56 "06033C104JAT2A" 0603 96.264,69.561 r0 top value=0.1uF
C57 "06033C104JAT2A" 0603 82.089,70.92 r180 top value=0.1uF
C58 "GRM188R71H221KA01D" 0603 145.531,127.857 r180 top value=220pF
C59 "TMK316AB7106KLHT" 1206_180 118.733,127.367 r270 top value=10uF
C60 "C4AUJBU4240M1WJ" FP-C4AUJBU4240M1WJ_RADIAL-MFG 91.456,98.18 r180 top value=2.4µF
C61 "06033C104JAT2A" 0603 119.392,124.282 r0 top value=0.1uF
C62 "GRM188R71H221KA01D" 0603 122.218,130.257 r270 top value=220pF
C63 "GRM1885C1H162JA01D" 0603 134.181,41.3 r90 top value=1600pF
C64 "GRM188R71H221KA01D" 0603 121.904,125.576 r90 top value=220pF
C65 "CGA4J3X7R1E225K125AB" 0805_HV 118.837,131.573 r270 top value=2.2uF
C66 "GRM1885C1H162JA01D" 0603 124.5,43.75 r90 top value=1600pF
C67 "C0603C331J5GACTU" 0603 177.619,78.105 r180 top value=330pF
C68 "TMK316AB7106KLHT" 1206_180 113.287,66.574 r270 top value=10uF
C69 "GRM188R71H221KA01D" 0603 119.152,68.056 r270 top value=220pF
C70 "06033C104JAT2A" 0603 112.762,62.863 r0 top value=0.1uF
C71 "06033C104JAT2A" 0603 128.972,58.628 r270 top value=0.1uF
C72 "TMK107BJ105KA-T" 0603 125.749,58.407 r270 top value=1uF
C73 "GRMJN7R61C206ME05" 0704 146.497,56.227 r270 top value=20uF
C74 "ZRB18AR61E106ME01L" FP-ZRB18AR61E106ME01L_0603-MFG 130.373,58.76 r90 top value=10µF
C75 "ZRB18AR61E106ME01L" FP-ZRB18AR61E106ME01L_0603-MFG 127.216,58.407 r90 top value=10µF
C76 "GRM1885C1H331JA01D" 0603 130.324,52.758 r270 top value=330pF
C77 "06033C104JAT2A" 0603 144.887,56.26 r270 top value=0.1uF
C78 "C0603C331J5GACTU" 0603 137.378,81.494 r90 top value=330pF
C79 "GRM188R71H221KA01D" 0603 117.555,63.034 r180 top value=220pF
C80 "CGA4J3X7R1E225K125AB" 0805_HV 112.514,70.863 r90 top value=2.2uF
C81 "885012206089" 0603 144.912,53.157 r90 top value=0.01uF
C82 "C0603C331J5GACTU" 0603 180.852,78.105 r0 top value=330pF
C83 "C0603C331J5GACTU" 0603 137.378,78.269 r270 top value=330pF
C84 "06033C104JAT2A" 0603 138.8,71.868 r270 top value=0.1uF
C85 "06033C104JAT2A" 0603 132.576,71.068 r0 top value=0.1uF
C86 "C0603C331J5GACTU" 0603 228.385,77.863 r180 top value=330pF
C87 "C0603C331J5GACTU" 0603 126.97,141.068 r180 top value=330pF
C88 "GRM188R71H221KA01D" 0603 128.596,65.097 r0 top value=220pF
C89 "GRM188R71H221KA01D" 0603 128.604,69.448 r0 top value=220pF
C90 "GRM188R71H221KA01D" 0603 130.839,126.414 r0 top value=220pF
C91 "C0603C331J5GACTU" 0603 231.782,77.863 r0 top value=330pF
C92 "GRM188R71H221KA01D" 0603 142.713,66.536 r180 top value=220pF
C93 "TMK316AB7106KLHT" 1206_180 112.887,78.197 r270 top value=10uF
C94 "C4AUJBU4240M1WJ" FP-C4AUJBU4240M1WJ_RADIAL-MFG 91.376,85.823 r180 top value=2.4µF
C95 "06033C104JAT2A" 0603 113.612,75.123 r0 top value=0.1uF
C96 "GRM188R71H221KA01D" 0603 119.043,82.113 r180 top value=220pF
C97 "C0603C331J5GACTU" 0603 130.208,140.867 r0 top value=330pF
C98 "GRM188R71H221KA01D" 0603 117.555,76.799 r180 top value=220pF
C99 "CGA4J3X7R1E225K125AB" 0805_HV 112.946,82.49 r270 top value=2.2uF
C100 "C1812C303KDGLCAUTO" 1812_254 200.183,59.349 r270 top value=0.03uF
C101 "C1812C303KDGLCAUTO" 1812_254 208.687,59.349 r270 top value=0.03uF
C102 "06033C104JAT2A" 0603 131.434,44.868 r0 top value=0.1uF
C103 "GRM1885C1H162JA01D" 0603 131.434,37.697 r0 top value=1600pF
C104 "GRM1885C1H162JA01D" 0603 25.533,169.408 r270 top value=1600pF
C105 "GRM1885C1H162JA01D" 0603 124.745,39.918 r90 top value=1600pF
C106 "C1812C303KDGLCAUTO" 1812_254 204.452,59.349 r270 top value=0.03uF
C107 "06033C104JAT2A" 0603 180.9,97.1 r90 top value=0.1uF
C108 "06033C104JAT2A" 0603 213.9,48.5 r90 top value=0.1uF
C109 "GRM1885C1H162JA01D" 0603 25.533,166.295 r270 top value=1600pF
C110 "C1812C303KDGLCAUTO" 1812_254 251.434,57.92 r270 top value=0.03uF
C111 "C1812C303KDGLCAUTO" 1812_254 246.809,57.92 r270 top value=0.03uF
C112 "GRM188R71H221KA01D" 0603 123.184,161.4 r90 top value=220pF
C113 "C1812C303KDGLCAUTO" 1812_254 256.24,57.92 r270 top value=0.03uF
C114 "ALH82D161DD600" FP-ALH82D161DD600_RADIAL-MFG 235.698,106.298 r180 top value=160µF
C115 "UWT1E101MCL1GS" UWT_630x770 134.566,158.148 r0 top value=100uF
C116 "GRM188R71H221KA01D" 0603 162.484,147.367 r180 top value=220pF
C117 "25SVP10M" SM_RADIAL_8MM 46.345,170.105 r180 top value=10uF
C118 "GRM188R71H221KA01D" 0603 165.626,147.333 r0 top value=220pF
C119 "06033C104JAT2A" 0603 152.5,158 r0 top value=0.1uF
C120 "GRM188R71H221KA01D" 0603 152.63,151.569 r180 top value=220pF
C121 "UWT1E101MCL1GS" UWT_630x770 35.125,171.248 r180 top value=100uF
C122 "GRM188R71H221KA01D" 0603 155.869,151.6 r0 top value=220pF
C123 "GRM1885C1H162JA01D" 0603 189.939,98.1 r270 top value=1600pF
C124 "06033C104JAT2A" 0603 177.046,81.631 r270 top value=0.1uF
C125 "06033C104JAT2A" 0603 140.177,81.855 r180 top value=0.1uF
C127 "C1812C303KDGLCAUTO" 1812_254 109.456,55.968 r270 top value=0.03uF
C128 "06033C104JAT2A" 0603 227.66,81.388 r270 top value=0.1uF
C129 "06033C104JAT2A" 0603 126.55,144.403 r270 top value=0.1uF
C130 "C1812C303KDGLCAUTO" 1812_254 113.397,55.976 r270 top value=0.03uF
C131 "C1812C303KDGLCAUTO" 1812_254 105.515,55.968 r270 top value=0.03uF
C132 "06033C104JAT2A" 0603 14.411,166.295 r270 top value=0.1uF
C135 "C1812C303KDGLCAUTO" 1812_254 120.592,105.196 r270 top value=0.03uF
C140 "C1812C303KDGLCAUTO" 1812_254 112.783,105.196 r270 top value=0.03uF
C141 "C1812C303KDGLCAUTO" 1812_254 116.688,105.196 r270 top value=0.03uF
C142 "GRM188R71H221KA01D" 0603 144,159.49 r90 top value=220pF
C143 "C4AQHBU5150P12J" FP-C4AQHBU5150P12J_RADIAL-MFG 267.4,107.45 r90 top value=15µF
C144 "UWT1E101MCL1GS" UWT_630x770 124.449,153.774 r270 top value=100uF
C146 "06033C104JAT2A" 0603 157.5,64.933 r180 top value=0.1uF
C151 "GRM188R71H221KA01D" 0603 128.596,66.55 r0 top value=220pF
C152 "GRM188R71H221KA01D" 0603 146.5,159.49 r90 top value=220pF
C155 "06033C104JAT2A" 0603 15.933,166.295 r270 top value=0.1uF
C224 "R533R456050P0M" FP-R533R456050P0M_RADIAL-MFG 24.468,17.95 r90 top value=5.6µF
D1 "C6D20065G" FP-C6D20065G_TO263-2-MFG 198.896,68.003 r270 top
D3 "C6D20065G" FP-C6D20065G_TO263-2-MFG 246.139,66.763 r270 top
D6 "BZT52C16-7-F" SOD-123 129,114.5 r270 top value=16V
D9 "BZT52C16-7-F" SOD-123 120.28,71.15 r180 top value=16V
D11 "SMBJ5350B-TP" FP-SMBJ5350B-TP_SMB-MFG 40.619,158.262 r0 top
D12 "ES1C-13-F" SMA 47.619,158.262 r180 top value=150V
D13 "150060VS75000" WL-SMCW_GREEN 53.036,171.097 r90 top value=Green
D14 "KG DELLS1.22-JGKH-24" "FP-KG DELLS1.22-JGKH-24_0603-MFG" 45.4,161.45 r0 top
D15 "150060VS75000" WL-SMCW_GREEN 128.507,171.711 r180 top value=Green
D16 "150060VS75000" WL-SMCW_GREEN 11.273,164.013 r0 top value=Green
D17 "KG DELLS1.22-JGKH-24" "FP-KG DELLS1.22-JGKH-24_0603-MFG" 177.101,66.109 r180 top
D18 "KG DELLS1.22-JGKH-24" "FP-KG DELLS1.22-JGKH-24_0603-MFG" 225.279,61.692 r270 top
D19 "KG DELLS1.22-JGKH-24" "FP-KG DELLS1.22-JGKH-24_0603-MFG" 120.704,118.376 r0 top
D20 "KG DELLS1.22-JGKH-24" "FP-KG DELLS1.22-JGKH-24_0603-MFG" 117.091,134.401 r90 top
D21 "KG DELLS1.22-JGKH-24" "FP-KG DELLS1.22-JGKH-24_0603-MFG" 115.384,69.329 r0 top
D22 "KG DELLS1.22-JGKH-24" "FP-KG DELLS1.22-JGKH-24_0603-MFG" 116.079,83.835 r0 top
FB1 "MH1608-601Y" FP-MH1608-601Y_0603-MFG 217.2,49.8 r270 top
FB2 "MH1608-601Y" FP-MH1608-601Y_0603-MFG 218,58.5 r270 top
FB3 "MH1608-601Y" FP-MH1608-601Y_0603-MFG 131.468,46.272 r0 top
FB4 "MH1608-601Y" FP-MH1608-601Y_0603-MFG 150.676,117.473 r270 top
FB5 "MH1608-601Y" FP-MH1608-601Y_0603-MFG 98.563,105.681 r180 top
FB6 "MH1608-601Y" FP-MH1608-601Y_0603-MFG 148.537,55.46 r180 top
FB7 "MH1608-601Y" FP-MH1608-601Y_0603-MFG 175.3,101.6 r270 top
FB9 "MH1608-601Y" FP-MH1608-601Y_0603-MFG 141.023,133.117 r180 top
FB10 "MH1608-601Y" FP-MH1608-601Y_0603-MFG 140.464,71.625 r270 top
FB11 "MH1608-601Y" FP-MH1608-601Y_0603-MFG 14.811,163.954 r0 top
FB12 "MH1608-601Y" FP-MH1608-601Y_0603-MFG 85.581,105.908 r90 top
FB13 "MH1608-601Y" FP-MH1608-601Y_0603-MFG 83.768,69.18 r180 top
FB14 "MH1608-601Y" FP-MH1608-601Y_0603-MFG 96.191,67.923 r180 top
FID1 "Fiducial" Fiducial10-20 256.5,80.613 r180 top
FID2 "Fiducial" Fiducial10-20 254.825,14.68 r180 top
FID3 "Fiducial" Fiducial10-20 1.984,164.395 r180 top
FID4 "Fiducial" Fiducial10-20 1.877,159.625 r90 bottom
FID5 "Fiducial" Fiducial10-20 26.5,46 r90 bottom
FID6 "Fiducial" Fiducial10-20 256.8,26.3 r90 bottom
J1 "74650073R" Wurth_WP-THRBU 182.807,118.984 r0 top
J2 "FCR7350R" FP-FCR7350R_CONN_BANANA_JACK-MFG -1.375,50.153 r0 top locked
J3 "FCR7350B" FP-FCR7350B_CONN_BANANA_JACK-MFG -1.375,36.15 r0 top locked
J4 "74650073R" Wurth_WP-THRBU 200.68,119.093 r270 top
J5 "FCR7350R" FP-FCR7350R_CONN_BANANA_JACK-MFG -1.675,21.95 r0 top locked
J6 "SHF-112-01-L-D-TH" FP-SHF-112-01-L-D-TH_HDR24-MFG 120.825,166.226 r180 top locked
J7 "FCR7350B" FP-FCR7350B_CONN_BANANA_JACK-MFG -1.475,7.75 r0 top locked
J8 "SHF-112-01-L-D-TH" FP-SHF-112-01-L-D-TH_HDR24-MFG 144.825,166.226 r180 top locked
J9 "FCR7350R" FP-FCR7350R_CONN_BANANA_JACK-MFG -1.475,92.55 r0 top locked
J10 "FCR7350R" FP-FCR7350R_CONN_BANANA_JACK-MFG -1.575,106.35 r0 top locked
J11 "FCR7350B" FP-FCR7350B_CONN_BANANA_JACK-MFG -1.375,64.75 r0 top locked
J12 "FCR7350B" FP-FCR7350B_CONN_BANANA_JACK-MFG -1.275,78.675 r0 top locked
K1 "G7L-2A-X DC12" "FP-G7L-2A-X DC12_PTH_RELAY_52MM5_35MM5-MFG" 27.4,136.8 r0 top
L1 "145451" FP-145451_PTH_IND_50MM0_50MM0-MFG 167.75,26.4 r270 top value=120uH
L2 "SDEM20161T-4R7MS" FP-SDEM20161T-4R7MS_SMD2-MFG 179.25,68.259 r270 top
L4 "145451" FP-145451_PTH_IND_50MM0_50MM0-MFG 254.046,26.053 r0 top value=120uH
L5 "SDEM20161T-4R7MS" FP-SDEM20161T-4R7MS_SMD2-MFG 223.993,66.507 r0 top
L6 "SRP1513CA-220M" FP-SRP1513CA-220M_SMD2-MFG 42.559,48.087 r270 top value=22uH
L7 "SDEM20161T-4R7MS" FP-SDEM20161T-4R7MS_SMD2-MFG 121.873,120.333 r270 top
L8 "SRP1513CA-220M" FP-SRP1513CA-220M_SMD2-MFG 42.325,22.75 r270 top value=22uH
L9 "145452" FP-145452_PTH_INDUCTOR_38MM5_60MM0-MFG 81.916,144 r0 top value=200uH
L10 "SDEM20161T-4R7MS" FP-SDEM20161T-4R7MS_SMD2-MFG 121.651,133.199 r270 top
L11 "SDEM20161T-4R7MS" FP-SDEM20161T-4R7MS_SMD2-MFG 116.793,71.665 r270 top
L13 "145452" FP-145452_PTH_INDUCTOR_38MM5_60MM0-MFG 84.518,27.626 r270 top value=200uH
L14 "SDEM20161T-4R7MS" FP-SDEM20161T-4R7MS_SMD2-MFG 116.023,81.84 r90 top
L18 "145454" FP-145454_PTH12-MFG 53.865,85.64 r270 top locked value=22uH
LBL1 "THT-14-423-10" Label_650x200 172.9,90.5 r0 top
LOGO1 "CAUTION HOT SURFACE" IEC_HotSurface_Small 121.993,5.365 r0 top
Logo2 "CE Mark" CE_Mark_5mm 169.3,73.7 r0 top
Logo3 "FCC disclaimer" FCC_disclaimer 177.356,100.525 r0 top
Logo4 "WEEE logo" WEEE_Minimum 208.365,100.237 r0 top
LOGO5 "DANGER HIGH VOLTAGE" IEC_HighVoltage_Small 169.1,82.5 r0 top
MP1 "9774015960R" FP-9774015960R_ROUND_SPACER_6MM0-MFG 124,18 r180 bottom
MP2 "9774015960R" FP-9774015960R_ROUND_SPACER_6MM0-MFG 170,58 r180 bottom
MP3 "9774015960R" FP-9774015960R_ROUND_SPACER_6MM0-MFG 165,170 r180 bottom locked
MP4 "9774015960R" FP-9774015960R_ROUND_SPACER_6MM0-MFG 5,170 r180 bottom locked
MP5 "9774015960R" FP-9774015960R_ROUND_SPACER_6MM0-MFG 42,5 r180 bottom
MP6 "9774015960R" FP-9774015960R_ROUND_SPACER_6MM0-MFG 216,5 r180 bottom
MP7 "9774015960R" FP-9774015960R_ROUND_SPACER_6MM0-MFG 248,86 r180 bottom
MP8 "9774015960R" FP-9774015960R_ROUND_SPACER_6MM0-MFG 114,144 r180 bottom
MP9 "9774015960R" FP-9774015960R_ROUND_SPACER_6MM0-MFG 131,105 r180 bottom locked
MP11 "9774015960R" FP-9774015960R_ROUND_SPACER_6MM0-MFG 83,60 r180 bottom locked
Q1 "CSD17318Q2" FP-CSD17318Q2_WSON6-MFG 40.669,163.366 r180 top
R1 "RG1608P-560-B-T5" 0603 180.601,71.645 r0 top value=56
R2 "PTCEL13R102SBE" FP-PTCEL13R102SBE_RADIAL-MFG 46.07,113.104 r0 top value=1000Ω
R3 "RG1608P-560-B-T5" 0603 142.197,139.948 r90 top value=56
R4 "RG1608P-560-B-T5" 0603 135.236,144.367 r0 top value=56
R5 "RG1608P-560-B-T5" 0603 142.195,143.211 r270 top value=56
R6 "RC0603FR-0720KL" 0603 183.976,71.89 r180 top value=20.0k
R7 "RT0603DRE071K67L" 0603 48.632,161.36 r180 top value=1.67k
R8 "RG1608P-560-B-T5" 0603 211.958,51.809 r90 top value=56
R9 "RT0603BRD0710RL" 0603 209.5,44.3 r0 top value=10.0
R10 "RT0603BRD0710RL" 0603 212.8,44.3 r180 top value=10.0
R11 "RG1608P-560-B-T5" 0603 226.842,70.312 r0 top value=56
R12 "RG1608P-103-B-T5" 0603 195.5,101.5 r0 top value=10.0k
R13 "RG1608P-560-B-T5" 0603 151.043,63.951 r270 top value=56
R14 "RG1608P-560-B-T5" 0603 160.1,62 r90 top value=56
R15 "RG1608P-560-B-T5" 0603 151.045,60.528 r90 top value=56
R16 "RC0603FR-0720KL" 0603 231.232,71.113 r180 top value=20.0k
R17 "CSS2H-2512K-3L00F" FP-CSS2H-2512K-3L00F_2512-MFG 199.331,28.75 r90 bottom value=3m
R18 "CSS2H-2512K-3L00F" FP-CSS2H-2512K-3L00F_2512-MFG 224.979,44.36 r90 bottom value=3m
R19 "RG1608P-560-B-T5" 0603 215.8,57.1 r90 top value=56
R20 "RT0603BRD0710RL" 0603 219,50.1 r90 top value=10.0
R21 "TNPV1206560KBEEN" TNPV1206 189.882,111.878 r270 top value=560k
R22 "ERJ-3EKF1202V" 0603 148.52,113.886 r180 top value=12.0k
R23 "RT0603DRE0738K8L" 0603 131.98,116.278 r0 top value=38.8k
R24 "RG1608P-560-B-T5" 0603 123.618,117.117 r180 top value=56
R25 "ERJ-3EKF1202V" 0603 152.164,117.511 r270 top value=12.0k
R26 "TNPV1206560KBEEN" TNPV1206 188.896,106.5 r270 top value=560k
R27 "RT0603BRD074K02L" 0603 153.691,117.49 r270 top value=4.02k
R28 "TNPV1206560KBEEN" TNPV1206 118.365,31.378 r90 top value=560k
R29 "RG1608P-103-B-T5" 0603 131.18,113.848 r270 top value=10.0k
R30 "TNPV1206560KBEEN" TNPV1206 118.307,36.6 r90 top value=560k
R31 "TNPV1206560KBEEN" TNPV1206 119.589,40.75 r0 top value=560k
R32 "RC0603FR-0720KL" 0603 124.348,112.415 r90 top value=20.0k
R33 "TNPV1206560KBEEN" TNPV1206 135.5,26 r90 top value=560k
R34 "RG1608P-560-B-T5" 0603 130.839,130.763 r180 top value=56
R35 "RG1608P-560-B-T5" 0603 130.839,127.854 r180 top value=56
R36 "TNPV1206560KBEEN" TNPV1206 135.5,30.75 r90 top value=560k
R37 "RG1608P-560-B-T5" 0603 145.544,126.319 r180 top value=56
R38 "RG1608P-560-B-T5" 0603 130.839,121.991 r180 top value=56
R39 "RG1608P-103-B-T5" 0603 140.566,139.948 r90 top value=10.0k
R40 "RG1608P-560-B-T5" 0603 123.865,130.257 r270 top value=56
R41 "TNPV1206560KBEEN" TNPV1206 191.586,103.067 r270 top value=560k
R42 "TNPV1206560KBEEN" TNPV1206 135.5,36 r90 top value=560k
R43 "TNPV1206560KBEEN" TNPV1206 16.836,158.025 r90 top value=560k
R44 "TNPV1206560KBEEN" TNPV1206 20.842,158.992 r0 top value=560k
R45 "RC0603FR-0720KL" 0603 123.555,125.576 r90 top value=20.0k
R46 "RG1608P-560-B-T5" 0603 180.125,100.7 r90 top value=56
R47 "ERJ-3EKF1202V" 0603 150,52.5 r180 top value=12.0k
R48 "RT0603DRE0738K8L" 0603 129.537,55.147 r0 top value=38.8k
R49 "RG1608P-560-B-T5" 0603 120.754,68.056 r270 top value=56
R50 "ERJ-3EKF1202V" 0603 149.012,54.032 r180 top value=12.0k
R51 "RG1608P-560-B-T5" 0603 145.519,129.353 r180 top value=56
R52 "RT0603BRD074K02L" 0603 146.497,53.157 r90 top value=4.02k
R53 "TNPV1206560KBEEN" TNPV1206 22.442,162.873 r90 top value=560k
R54 "RG1608P-103-B-T5" 0603 128.724,52.783 r270 top value=10.0k
R56 "RT0603BRD0710RL" 0603 100.356,111.048 r180 top value=10.0
R57 "RC0603FR-0720KL" 0603 117.555,64.532 r180 top value=20.0k
R58 "RT0603BRD0710RL" 0603 100.265,109.374 r180 top value=10.0
R59 "RG1608P-560-B-T5" 0603 128.604,70.94 r180 top value=56
R60 "RG1608P-560-B-T5" 0603 128.607,68.004 r180 top value=56
R61 "RG1608P-560-B-T5" 0603 82.247,111.087 r0 top value=56
R62 "RG1608P-560-B-T5" 0603 142.713,65.069 r180 top value=56
R63 "RG1608P-560-B-T5" 0603 128.604,62.094 r180 top value=56
R64 "RG1608P-103-B-T5" 0603 140.564,143.21 r270 top value=10.0k
R65 "RG1608P-560-B-T5" 0603 119.043,80.611 r180 top value=56
R66 "RG1608P-560-B-T5" 0603 82.247,109.43 r0 top value=56
R67 "RT0603BRD0710RL" 0603 100.378,71.272 r90 top value=10.0
R68 "TNPV1206560KBEEN" TNPV1206 32.825,158.025 r90 top value=560k
R69 "TNPV1206560KBEEN" TNPV1206 32.825,163.041 r90 top value=560k
R70 "RC0603FR-0720KL" 0603 117.555,78.269 r180 top value=20.0k
R71 "RT0603BRD0710RL" 0603 220.6,49.3 r90 top value=10.0
R72 "RG1608P-560-B-T5" 0603 214.4,55.354 r90 top value=56
R73 "RG1608P-560-B-T5" 0603 81.615,73.9 r0 top value=56
R74 "TNPV1206560KBEEN" TNPV1206 30.666,166.532 r180 top value=560k
R75 "RG1608P-560-B-T5" 0603 177.715,74.959 r0 top value=56
R76 "RG1608P-560-B-T5" 0603 134.333,81.494 r270 top value=56
R77 "RG1608P-560-B-T5" 0603 180.877,74.959 r180 top value=56
R78 "RG1608P-560-B-T5" 0603 134.333,78.269 r90 top value=56
R79 "RG1608P-103-B-T5" 0603 177.715,76.459 r0 top value=10.0k
R80 "RG1608P-103-B-T5" 0603 135.833,81.494 r270 top value=10.0k
R81 "RG1608P-103-B-T5" 0603 180.877,76.459 r180 top value=10.0k
R82 "RG1608P-103-B-T5" 0603 135.833,78.269 r90 top value=10.0k
R83 "RG1608P-560-B-T5" 0603 228.385,74.863 r0 top value=56
R84 "RG1608P-560-B-T5" 0603 127.025,137.837 r0 top value=56
R85 "RG1608P-560-B-T5" 0603 231.807,74.863 r180 top value=56
R86 "RG1608P-560-B-T5" 0603 127.454,44.793 r0 top value=56
R87 "RG1608P-560-B-T5" 0603 134.064,44.453 r90 top value=56
R88 "PTCEL13R102SBE" FP-PTCEL13R102SBE_RADIAL-MFG 25.732,113.104 r0 top value=1000Ω
R89 "RG1608P-560-B-T5" 0603 130.283,137.838 r180 top value=56
R90 "RG1608P-103-B-T5" 0603 228.385,76.244 r0 top value=10.0k
R91 "RG1608P-103-B-T5" 0603 127.025,139.468 r0 top value=10.0k
R92 "RG1608P-103-B-T5" 0603 231.807,76.244 r180 top value=10.0k
R93 "RG1608P-103-B-T5" 0603 130.283,139.47 r180 top value=10.0k
R94 "TNPV1206560KBEEN" TNPV1206 141,32 r90 top value=560k
R95 "RG1608P-560-B-T5" 0603 81.6,72.5 r0 top value=56
R96 "RT0603BRD0710RL" 0603 98.945,71.272 r90 top value=10.0
R98 "TNPV1206560KBEEN" TNPV1206 141,37 r90 top value=560k
R99 "RG1608P-560-B-T5" 0603 178.116,100.22 r90 top value=56
R100 "TNPV1206560KBEEN" TNPV1206 139.1,41 r180 top value=560k
R101 "TNPV1206560KBEEN" TNPV1206 129.492,26 r90 top value=560k
R102 "TNPV1206560KBEEN" TNPV1206 127.922,30.068 r180 top value=560k
R103 "TNPV1206560KBEEN" TNPV1206 124,31.75 r90 top value=560k
R104 "RG1608P-103-B-T5" 0603 135.75,41.3 r90 top value=10.0k
R105 "RC0603JR-075K6L" 0603 174.956,67.206 r270 top value=5.6k
R106 "RG1608P-103-B-T5" 0603 131.434,36.222 r180 top value=10.0k
R107 "RG1608P-103-B-T5" 0603 122.825,43.75 r90 top value=10.0k
R108 "RG1608P-560-B-T5" 0603 161.385,152.683 r90 top value=56
R109 "RG1608P-560-B-T5" 0603 161.684,143.53 r90 top value=56
R112 "RG1608P-560-B-T5" 0603 166.49,143.598 r90 top value=56
R113 "RG1608P-560-B-T5" 0603 166.745,152.683 r90 top value=56
R116 "RG1608P-560-B-T5" 0603 149.907,157.119 r90 top value=56
R117 "RG1608P-560-B-T5" 0603 150.382,150.8 r270 top value=56
R120 "RG1608P-560-B-T5" 0603 156.733,147.872 r90 top value=56
R121 "RG1608P-560-B-T5" 0603 155.069,158.819 r90 top value=56
R125 "RG1608P-103-B-T5" 0603 155.869,150.108 r0 top value=10.0k
R127 "RG1608P-103-B-T5" 0603 152.63,150.108 r180 top value=10.0k
R129 "RG1608P-103-B-T5" 0603 165.626,145.869 r0 top value=10.0k
R131 "RG1608P-103-B-T5" 0603 162.484,145.864 r180 top value=10.0k
R132 "RC0603JR-075K6L" 0603 223.705,61.76 r270 top value=5.6k
R133 "RC0603JR-075K6L" 0603 123.778,120.24 r270 top value=5.6k
R134 "CSS2H-2512K-1L50FE" FP-CSS2H-2512K-1L80FE_2512-MFG 102.33,119.51 r0 bottom value=1.5m
R135 "RC0603JR-075K6L" 0603 119.435,135.296 r180 top value=5.6k
R136 "RC0603JR-075K6L" 0603 117.194,68.973 r90 top value=5.6k
R137 "CSS2H-2512K-1L50FE" FP-CSS2H-2512K-1L80FE_2512-MFG 95.55,64.236 r0 bottom value=1.5m
R138 "RC0603JR-075K6L" 0603 118.994,84.205 r180 top value=5.6k
R139 "RG1608P-103-B-T5" 0603 27.031,169.408 r90 top value=10.0k
R140 "RG1608P-103-B-T5" 0603 122.987,39.918 r90 top value=10.0k
R141 "RG1608P-103-B-T5" 0603 27.031,166.295 r270 top value=10.0k
R144 "RNCF0603TKY1K00" 0603 43.602,164.111 r180 top value=1.00k
R145 "RG1608P-103-B-T5" 0603 40.302,167.315 r180 top value=10.0k
R146 "RG1608P-560-B-T5" 0603 210.3,51.8 r90 top value=56
R147 "RT0603DRE071K67L" 0603 53.036,167.331 r90 top value=1.67k
R149 "RG1608P-560-B-T5" 0603 129.004,36.947 r270 top value=56
R150 "RG1608P-560-B-T5" 0603 26.258,171.735 r0 top value=56
R151 "RG1608P-560-B-T5" 0603 125.904,37.422 r0 top value=56
R152 "RG1608P-560-B-T5" 0603 26.306,163.927 r0 top value=56
R153 "CRCW0603499RFKEAC" 0603 132.27,171.775 r180 top value=499
R154 "RT0603DRE07218RL" 0603 8.569,162.22 r0 top value=218
R155 "RG1608P-560-B-T5" 0603 130.839,123.463 r180 top value=56
R156 "RG1608P-103-B-T5" 0603 152.66,63.951 r270 top value=10.0k
R157 "RG1608P-103-B-T5" 0603 152.661,60.528 r90 top value=10.0k
R158 "RG1608P-560-B-T5" 0603 128.6,63.623 r180 top value=56
R159 "RG1608P-560-B-T5" 0603 142.713,68.004 r180 top value=56
TP1 "5001" Keystone5001 154.28,146.674 r0 top
TP2 "S2751-46R" Harwin_S2751-46R 112.25,133 r180 top
TP4 "5001" Keystone5001 128.324,78.415 r90 top
TP5 "5001" Keystone5001 147.508,62.931 r180 top
TP6 "5001" Keystone5001 207.4,47.329 r180 top
TP9 "S2751-46R" Harwin_S2751-46R 116.167,116.952 r90 top
TP10 "S2751-46R" Harwin_S2751-46R 92.5,62.635 r270 top
TP12 "S2751-46R" Harwin_S2751-46R 190.866,59.39 r180 top
TP16 "S2751-46R" Harwin_S2751-46R 238.234,58.082 r180 top
TP35 "S2751-46R" Harwin_S2751-46R 202.367,107.647 r90 top
TP39 "S2751-46R" Harwin_S2751-46R 48.652,59.25 r90 top
TP40 "S2751-46R" Harwin_S2751-46R 182.25,109.883 r90 top
TP41 "S2751-46R" Harwin_S2751-46R 34.75,35.534 r90 top
TP42 "5001" Keystone5001 206.492,112.741 r90 top
TP43 "S2751-46R" Harwin_S2751-46R 49.25,33.804 r90 top
TP44 "S2751-46R" Harwin_S2751-46R 34.25,3.79 r90 top
TP45 "S2751-46R" Harwin_S2751-46R 10.75,115.25 r90 top
TP46 "S2751-46R" Harwin_S2751-46R 37.022,113.252 r90 top
U1 "LMG3522R030Q" RQS0052C-C01-MFG 185.141,61.684 r180 bottom
U2 "SN74LVC2G34DBVR" DBV0006A_N 164.076,150.583 r90 top
U3 "INA181A2IDBV" DBV0006A_N 211.2,48.4 r0 top
U4 "LMG3522R030Q" RQS0052C-C01-MFG 232.184,60.75 r180 bottom
U5 "INA181A2IDBV" DBV0006A_N 218.6,55.2 r0 top
U6 "UCC14131QDWNRQ1" DWJ0036A-MFG 140.324,118.465 r180 top
U7 "LMG3522R030Q" RQS0052C-C01-MFG 113.6,113.529 r90 bottom
U8 "SN74LVC1G08DBVT" DBV0005A_N 135.814,141.735 r180 top
U9 "ISO7741FDBQR" DBQ0016A-MFG 138.193,127.815 r0 top
U10 "LMG3522R030Q" RQS0052C-C01-MFG 113.6,127.156 r90 bottom
U11 "UCC14131QDWNRQ1" DWJ0036A-MFG 137.712,57.595 r180 top
U12 "LMG3522R030Q" RQS0052C-C01-MFG 107.562,64.324 r90 bottom
U13 "SN74LVC1G08DBVT" DBV0005A_N 157.3,62.175 r0 top
U14 "ISO7741FDBQR" DBQ0016A-MFG 136.216,67.445 r0 top
U15 "LMG3522R030Q" RQS0052C-C01-MFG 107.562,77.641 r90 bottom
U16 "OPA2388IDR" D0008A-MFG 129.444,41.338 r0 top
U17 "SN74LVC1G08DBVT" DBV0005A_N 179.71,81.253 r90 top
U18 "SN74LVC1G08DBVT" DBV0005A_N 140.201,78.513 r0 top
U19 "SN74LVC1G08DBVT" DBV0005A_N 230.64,80.888 r90 top
U20 "SN74LVC1G08DBVT" DBV0005A_N 129.333,144.22 r90 top
U21 "AMC1302DWV" DWV0008A 90.578,109.759 r180 top
U22 "AMC1302DWV" DWV0008A 90.014,73.025 r180 top
U23 "OPA388IDR" D0008A_L 20.9,167.9 r180 top
U25 "SN74LVC2G34DBVR" DBV0006A_N 152.805,154.911 r90 top
U26 "OPA388IDR" D0008A_L 185.4,97.8 r180 top
ZZ1 "This Assembly Note is for PCB labels only" AssemblyNoteLabel 290.572,106.45 r0 top
ZZ2 "These assemblies are ESD sensitive, ESD precautions shall be observed." AssemblyNote 290.064,110.45 r0 top
ZZ3 "These assemblies must be clean and free from flux and all contaminants. Use of no clean flux is not acceptable." AssemblyNote 290.325,114.45 r0 top
ZZ4 "These assemblies must comply with workmanship standards IPC-A-610 Class 2, unless otherwise specified." AssemblyNote 290.325,117.95 r0 top

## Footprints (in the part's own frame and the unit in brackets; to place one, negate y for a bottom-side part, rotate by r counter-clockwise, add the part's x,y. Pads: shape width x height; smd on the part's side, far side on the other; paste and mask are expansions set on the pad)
0603 [mm] "0603 from SM-752 data"
  rect 1x0.95 smd: 1(-0.8,0) 2(0.8,0)
  silkscreen extent -1.52,-0.69 1.52,0.69, body extent -0.87,-0.47 0.87,0.47, height 1
0704 [mm] "Murata"
  rrect11% 1x1.2 smd: 1(-0.9,0) 2(0.9,0)
  silkscreen extent -0.25,-0.77 0.25,0.8, body extent -0.95,-0.55 0.95,0.55, height 0.8
0805_HV [mil] "0805 with 30mil clearance between pads"
  rect 50x63 smd: 1(-40,0) 2(40,0)
  silkscreen extent -74,-40 74,40, body extent -43,-29 43,29, height 57
1206_180 [mm] "1206_180"
  rect 1.1x1.6 smd: 1(-1.7,0) 2(1.7,0)
  silkscreen extent -0.9,-1 0.9,1, body extent -1.75,-0.95 1.75,0.95, height 1.8
1812_254 [mm] "SMD, 2-Leads, Body 4.8x3.4mm"
  rect 1.6x3.4 smd: 1(-2,0) 2(2,0)
  silkscreen extent -0.8,-1.7 0.8,1.7, body extent -2.4,-1.7 2.4,1.7, height 2.54
AssemblyNote [mm] "Assembly Note"
AssemblyNoteLabel [mm] "Assembly Note for PCB Labels"
CE_Mark_5mm [mm] "Minimum text height for CE Mark"
  silkscreen extent -3.5,-2.5 3.5,2.5
D0008A-MFG [mm]
  rrect17% 1.55x0.6 smd paste+0 mask+0: 1(-2.7,1.905) 2(-2.7,0.635) 3(-2.7,-0.635) 4(-2.7,-1.905) 5(2.7,-1.905) 6(2.7,-0.635) 7(2.7,0.635) 8(2.7,1.905)
  silkscreen extent -4.17,-2.5 1.5,2.5, body extent -3.57,-2.75 3.57,2.75, height 0.25
D0008A_L [mm] "SOIC, 8-Leads, Body 4.9x3.9mm, Pitch 1.27mm, IPC High Density"
  oval 1.25x0.55 smd: 1(-2.625,1.905) 2(-2.625,0.635) 3(-2.625,-0.635) 4(-2.625,-1.905) 5(2.625,-1.905) 6(2.625,-0.635) 7(2.625,0.635) 8(2.625,1.905)
  silkscreen extent -3.1,-2.5 0.9,2.5, body extent -3,-2.45 3,2.45, height 1.63
DBQ0016A-MFG [mm]
  rrect24% 1.6x0.41 smd paste+0 mask+0: 1(-2.7,2.222) 2(-2.7,1.587) 3(-2.7,0.953) 4(-2.7,0.318) 5(-2.7,-0.318) 6(-2.7,-0.953) 7(-2.7,-1.587) 8(-2.7,-2.222) 9(2.7,-2.222) 10(2.7,-1.587) 11(2.7,-0.953) 12(2.7,-0.318) 13(2.7,0.318) 14(2.7,0.953) 15(2.7,1.587) 16(2.7,2.222)
  silkscreen extent -4.17,-2.5 1.5,2.5, body extent -3.6,-2.75 3.6,2.75, height 0.25
DBV0005A_N [mm] "SOT23, 5-Leads, Body 2.9x1.6mm, Pitch 0.95mm, Lead Span 2.8mm, IPC Medium Density"
  rrect17% 1x0.6 smd: 1(-1.375,0.95) 2(-1.375,0) 3(-1.375,-0.95) 4(1.375,-0.95) 5(1.375,0.95)
  silkscreen extent -0.25,-1.55 0.25,1.55, body extent -1.42,-1.46 1.42,1.46, height 1.09
DBV0006A_N [mm] "SOT23, 6-Leads, Body 2.9x1.6mm, Pitch 0.95mm, Lead Span 2.8mm, IPC Medium Density"
  rrect17% 1x0.6 smd: 1(-1.375,0.95) 2(-1.375,0) 3(-1.375,-0.95) 4(1.375,-0.95) 5(1.375,0) 6(1.375,0.95)
  silkscreen extent -1.68,-1.55 0.5,1.55, body extent -1.42,-1.46 1.42,1.46, height 1.12
DWJ0036A-MFG [mm]
  rrect22% 1.85x0.45 smd paste+0 mask+0: 1(-4.975,5.525) 2(-4.975,4.875) 3(-4.975,4.225) 4(-4.975,3.575) 5(-4.975,2.925) 6(-4.975,2.275) 7(-4.975,1.625) 8(-4.975,0.975) 9(-4.975,0.325) 10(-4.975,-0.325) 11(-4.975,-0.975) 12(-4.975,-1.625) 13(-4.975,-2.275) 14(-4.975,-2.925) 15(-4.975,-3.575) 16(-4.975,-4.225) 17(-4.975,-4.875) 18(-4.975,-5.525) 19(4.975,-5.525) 20(4.975,-4.875) 21(4.975,-4.225) 22(4.975,-3.575) 23(4.975,-2.925) 24(4.975,-2.275) 25(4.975,-1.625) 26(4.975,-0.975) 27(4.975,-0.325) 28(4.975,0.325) 29(4.975,0.975) 30(4.975,1.625) 31(4.975,2.275) 32(4.975,2.925) 33(4.975,3.575) 34(4.975,4.225) 35(4.975,4.875) 36(4.975,5.525)
  silkscreen extent -6.58,-6.47 3.8,6.47, body extent -5.15,-6.42 5.15,6.42, height 3.55
DWV0008A [mm] "SOIC, 8-Leads, Body 5.95x7.6mm (max), Pitch 1.27mm"
  rrect17% 1.8x0.6 smd: 1(-5.45,1.905) 2(-5.45,0.635) 3(-5.45,-0.635) 4(-5.45,-1.905) 5(5.45,-1.905) 6(5.45,-0.635) 7(5.45,0.635) 8(5.45,1.905)
  silkscreen extent -6.25,-2.95 2.98,2.95, body extent -5.77,-2.92 5.77,2.93, height 2.67
FCC_disclaimer [mm]
Fiducial10-20 [mm]
  round 1 smd mask+0.5: 1(0,0)
  Top Layer keep-out circle w1.178: c0,0 r0.5
FP-145451_PTH_IND_50MM0_50MM0-MFG [mm]
  rrect5% 2.2x2.2 hole 1.5 paste-2539.97 mask+0: 1(-21.9,15)
  round 2.2 hole 1.5 paste-2539.97 mask+0: 2(-21.9,10) 3(-21.9,5) 4(-21.9,-5) 5(-21.9,-10) 6(-21.9,-15) 7(21.9,-15) 8(21.9,-10) 9(21.9,-5) 10(21.9,5) 11(21.9,10) 12(21.9,15)
  silkscreen extent -25.62,-25 25,25, body extent -26,-26 26,26, height 0.25
FP-145452_PTH_INDUCTOR_38MM5_60MM0-MFG [mm]
  rrect4% 2.8x2.8 hole 1.5 paste-2539.97 mask+0: 1(-19.25,12.95)
  round 2.8 hole 1.5 paste-2539.97 mask+0: 2(-19.25,8.95) 3(-19.25,-8.95) 4(-19.25,-12.95) 5(19.25,-12.95) 6(19.25,-8.95) 7(19.25,8.95) 8(19.25,12.95)
  silkscreen extent -26.85,-30 26.25,30, body extent -26.35,-30.1 26.35,30.1, height 0.25
FP-145454_PTH12-MFG [mm]
  rrect5% 2.2x2.2 hole 1.5 paste-2539.97 mask+0: 1(-17.5,15)
  round 2.2 hole 1.5 paste-2539.97 mask+0: 2(-17.5,10) 3(-17.5,5) 4(-17.5,-5) 5(-17.5,-10) 6(-17.5,-15) 7(17.5,-15) 8(17.5,-10) 9(17.5,-5) 10(17.5,5) 11(17.5,10) 12(17.5,15)
  silkscreen extent -21.62,-20.25 20.9,20.25, body extent -21.9,-21.25 21.9,21.25, height 0.25
FP-9774015960R_ROUND_SPACER_6MM0-MFG [mm]
  round 5.245 smd paste-1000 mask-1000: 1(0,0)
  round 4.4 hole 4.4 unplated paste-2539.97 mask+0: ""(0,0)
  Top Layer circle w1.5: c0,0 r2.95
  silkscreen extent -4.15,-4.15 4.15,4.15, body extent -3,-3 3,3, height 1.6
FP-ALH82D161DD600_RADIAL-MFG [mm]
  rrect3% 3.05x3.05 hole 2 paste-2539.97 mask+0: 1(-5,0)
  round 3.05 hole 2 paste-2539.97 mask+0: 2(5,0)
  silkscreen extent -18,-18 18,18, body extent -18.1,-18.1 18.1,18.1, height 0.25
FP-C4AKOBU4270A3YJ_RADIAL-MFG [mm]
  rrect5% 2.15x2.15 hole 1.4 paste-2539.97 mask+0: 1(-13.75,0)
  round 2.15 hole 1.4 paste-2539.97 mask+0: 2(13.75,0)
  silkscreen extent -16.35,-7.35 16.35,7.35, body extent -16.45,-7.45 16.45,7.45, height 0.25
FP-C4AQHBU5150P12J_RADIAL-MFG [mm]
  rrect6% 1.55x1.55 hole 1 paste-2539.97 mask+0: 1(-13.75,0)
  round 1.55 hole 1 paste-2539.97 mask+0: 2(13.75,0)
  silkscreen extent -16,-11.15 16,11.15, body extent -16.1,-11.25 16.1,11.25, height 0.25
FP-C4AUJBU4240M1WJ_RADIAL-MFG [mm]
  rrect6% 1.55x1.55 hole 1 paste-2539.97 mask+0: 1(-13.75,0)
  round 1.55 hole 1 paste-2539.97 mask+0: 2(13.75,0)
  silkscreen extent -16.35,-5.85 16.35,5.85, body extent -16.45,-5.95 16.45,5.95, height 0.25
FP-C4AUJBU4600M18J_RADIAL-MFG [mm]
  rrect6% 1.55x1.55 hole 1 paste-2539.97 mask+0: 1(-13.75,0)
  round 1.55 hole 1 paste-2539.97 mask+0: 2(13.75,0)
  silkscreen extent -16.35,-8.35 16.35,8.35, body extent -16.45,-8.45 16.45,8.45, height 0.25
FP-C6D20065G_TO263-2-MFG [mm]
  rrect6% 1.54x3.56 smd paste+0 mask+0: 1(-2.54,-7.993) 2(2.54,-7.993)
  rrect1% 10.69x8.89 smd paste+0 mask+0: 3(0,1.773)
  silkscreen extent -5.14,-4.7 5.14,-3.05, body extent -5.45,-9.87 5.45,6.32, height 0.25
FP-CSD17318Q2_WSON6-MFG [mm]
  rrect33% 0.45x0.3 smd paste+0 mask+0: 1(-0.975,0.65) 2(-0.975,0) 3(-0.975,-0.65) 4(0.975,-0.65) 5(0.975,0) 6(0.975,0.65)
  rrect33% 0.75x0.3 smd paste-1000 mask+0: 7(0.095,-0.65)
  rrect11% 1x0.95 smd paste-1000 mask+0: 8(0,0.325)
  body extent -1.3,-1.15 1.3,1.15, height 0.25
FP-CSS2H-2512K-1L80FE_2512-MFG [mm]
  rrect6% 1.8x3.4 smd paste+0 mask+0: 1(-2.6,0) 2(2.6,0)
  silkscreen extent -1.33,-1.63 1.33,1.63, body extent -3.17,-1.53 3.17,1.53, height 1.21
